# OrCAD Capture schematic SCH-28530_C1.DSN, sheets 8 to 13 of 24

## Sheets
8 08 SYSTEM: size C
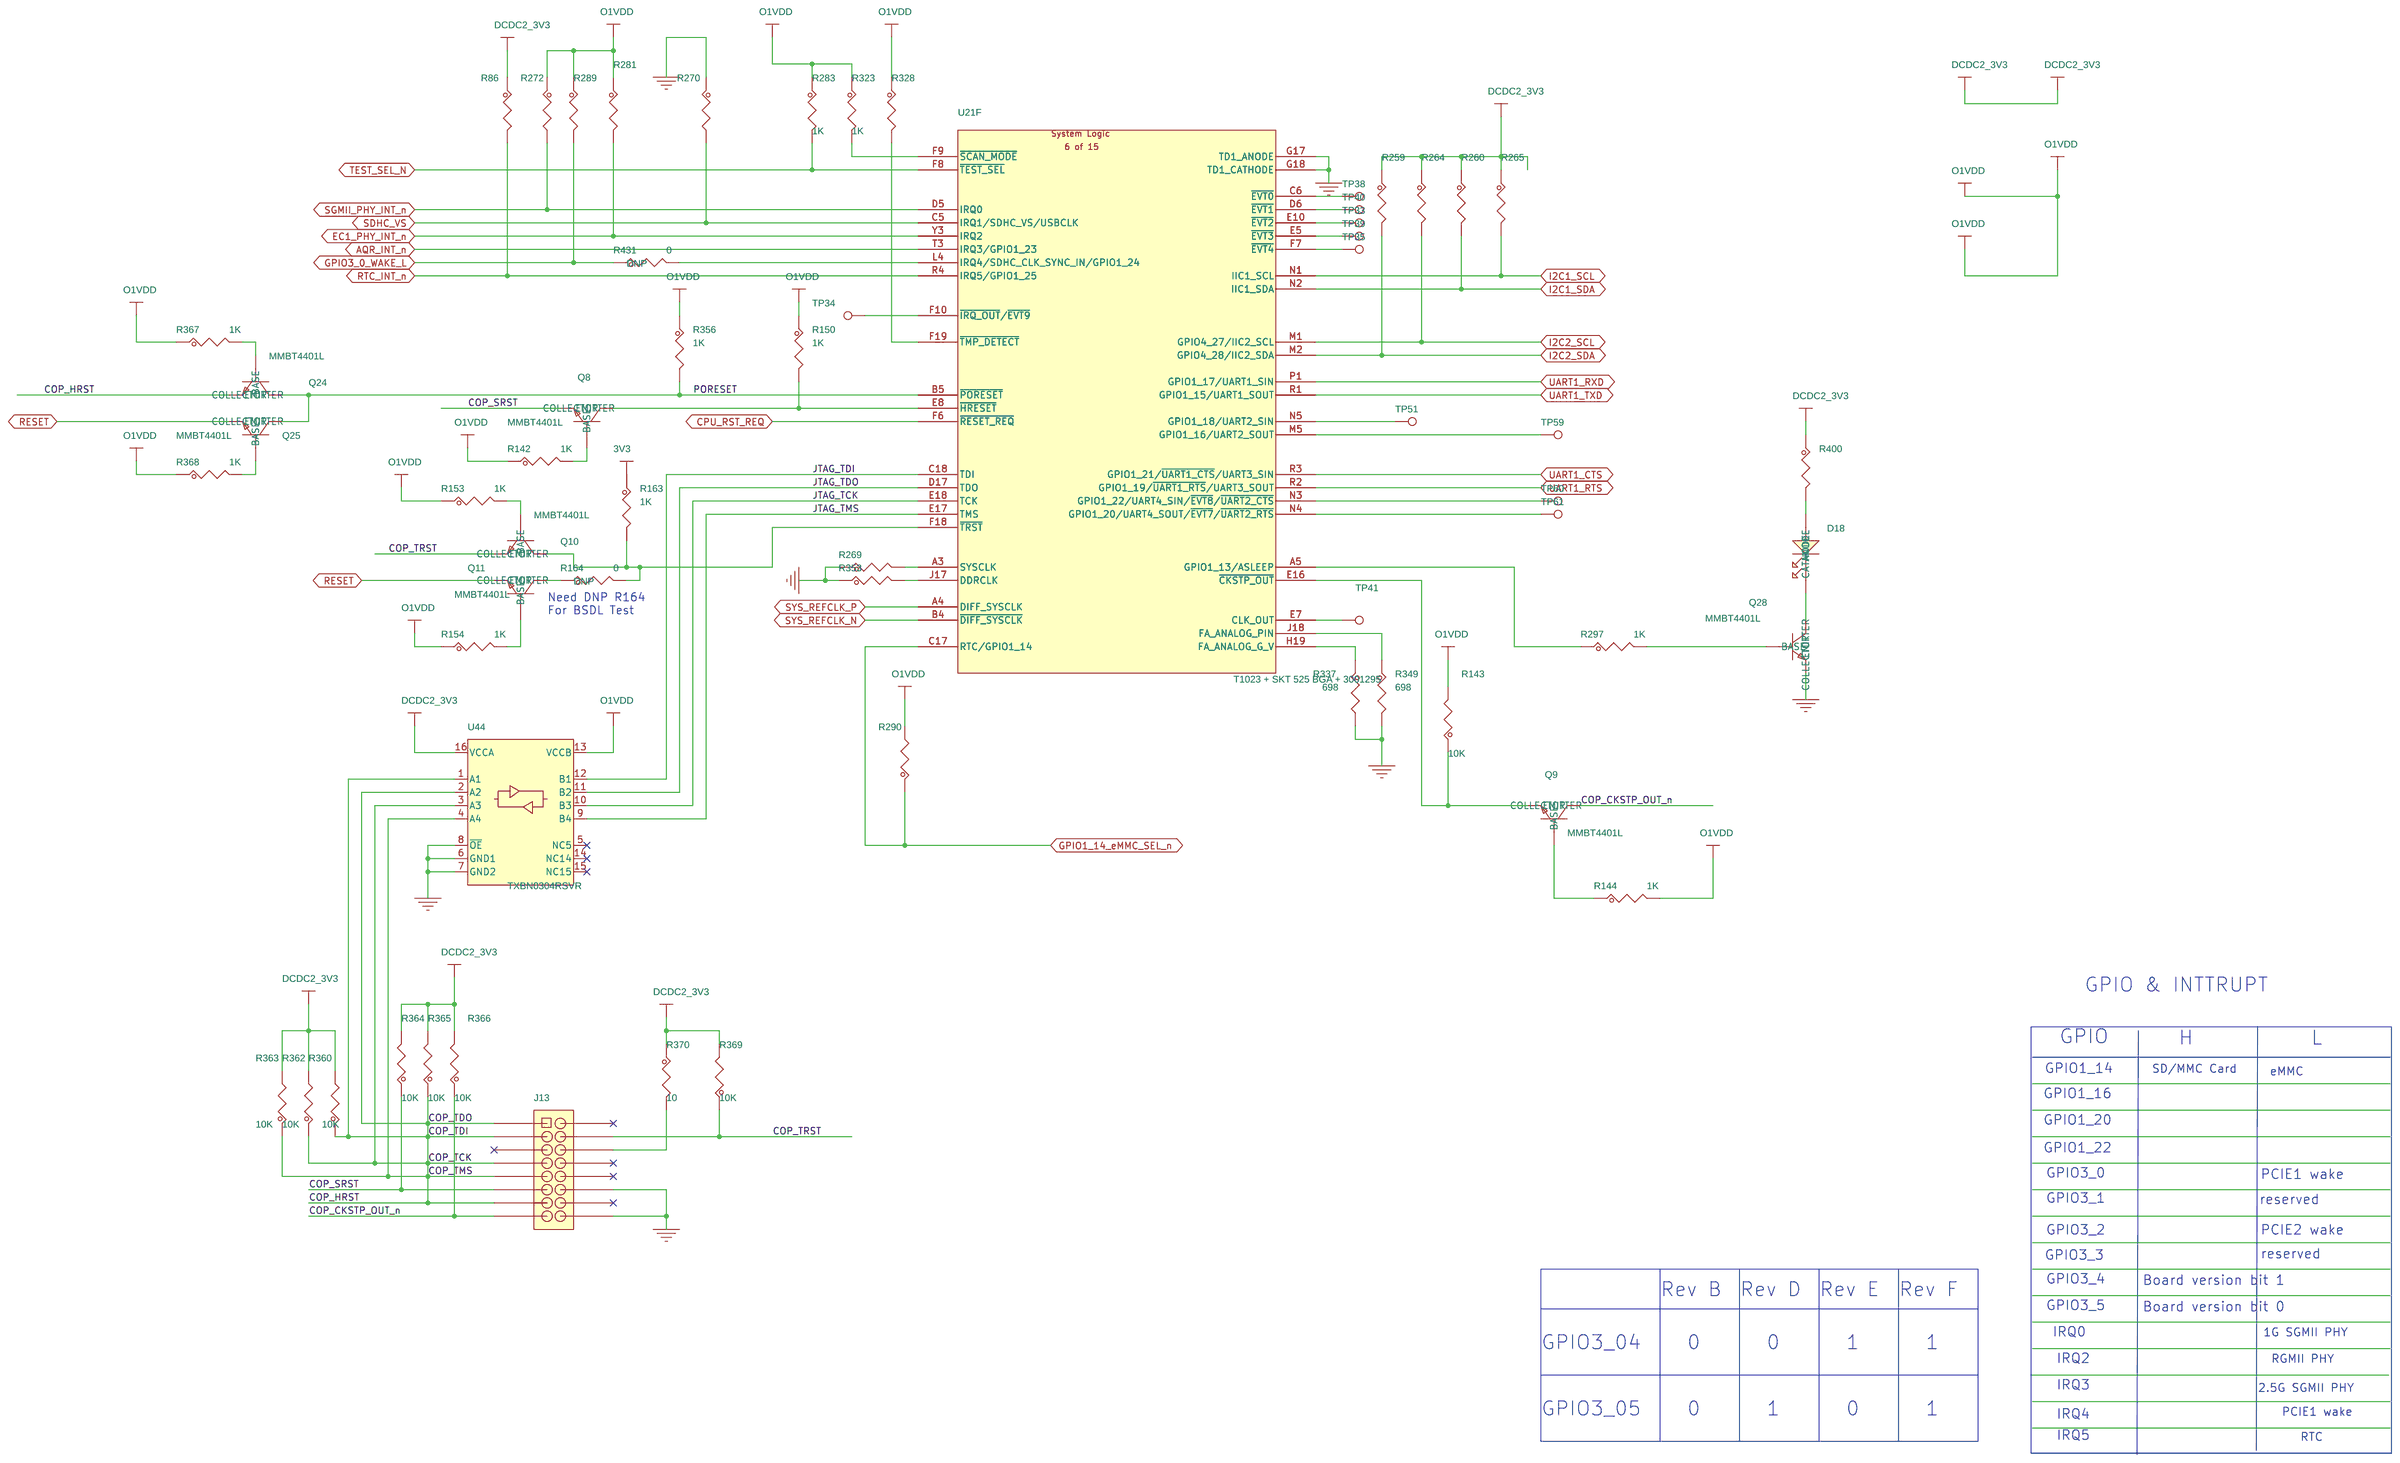
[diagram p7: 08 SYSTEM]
9 09 EC&SerDes: size B
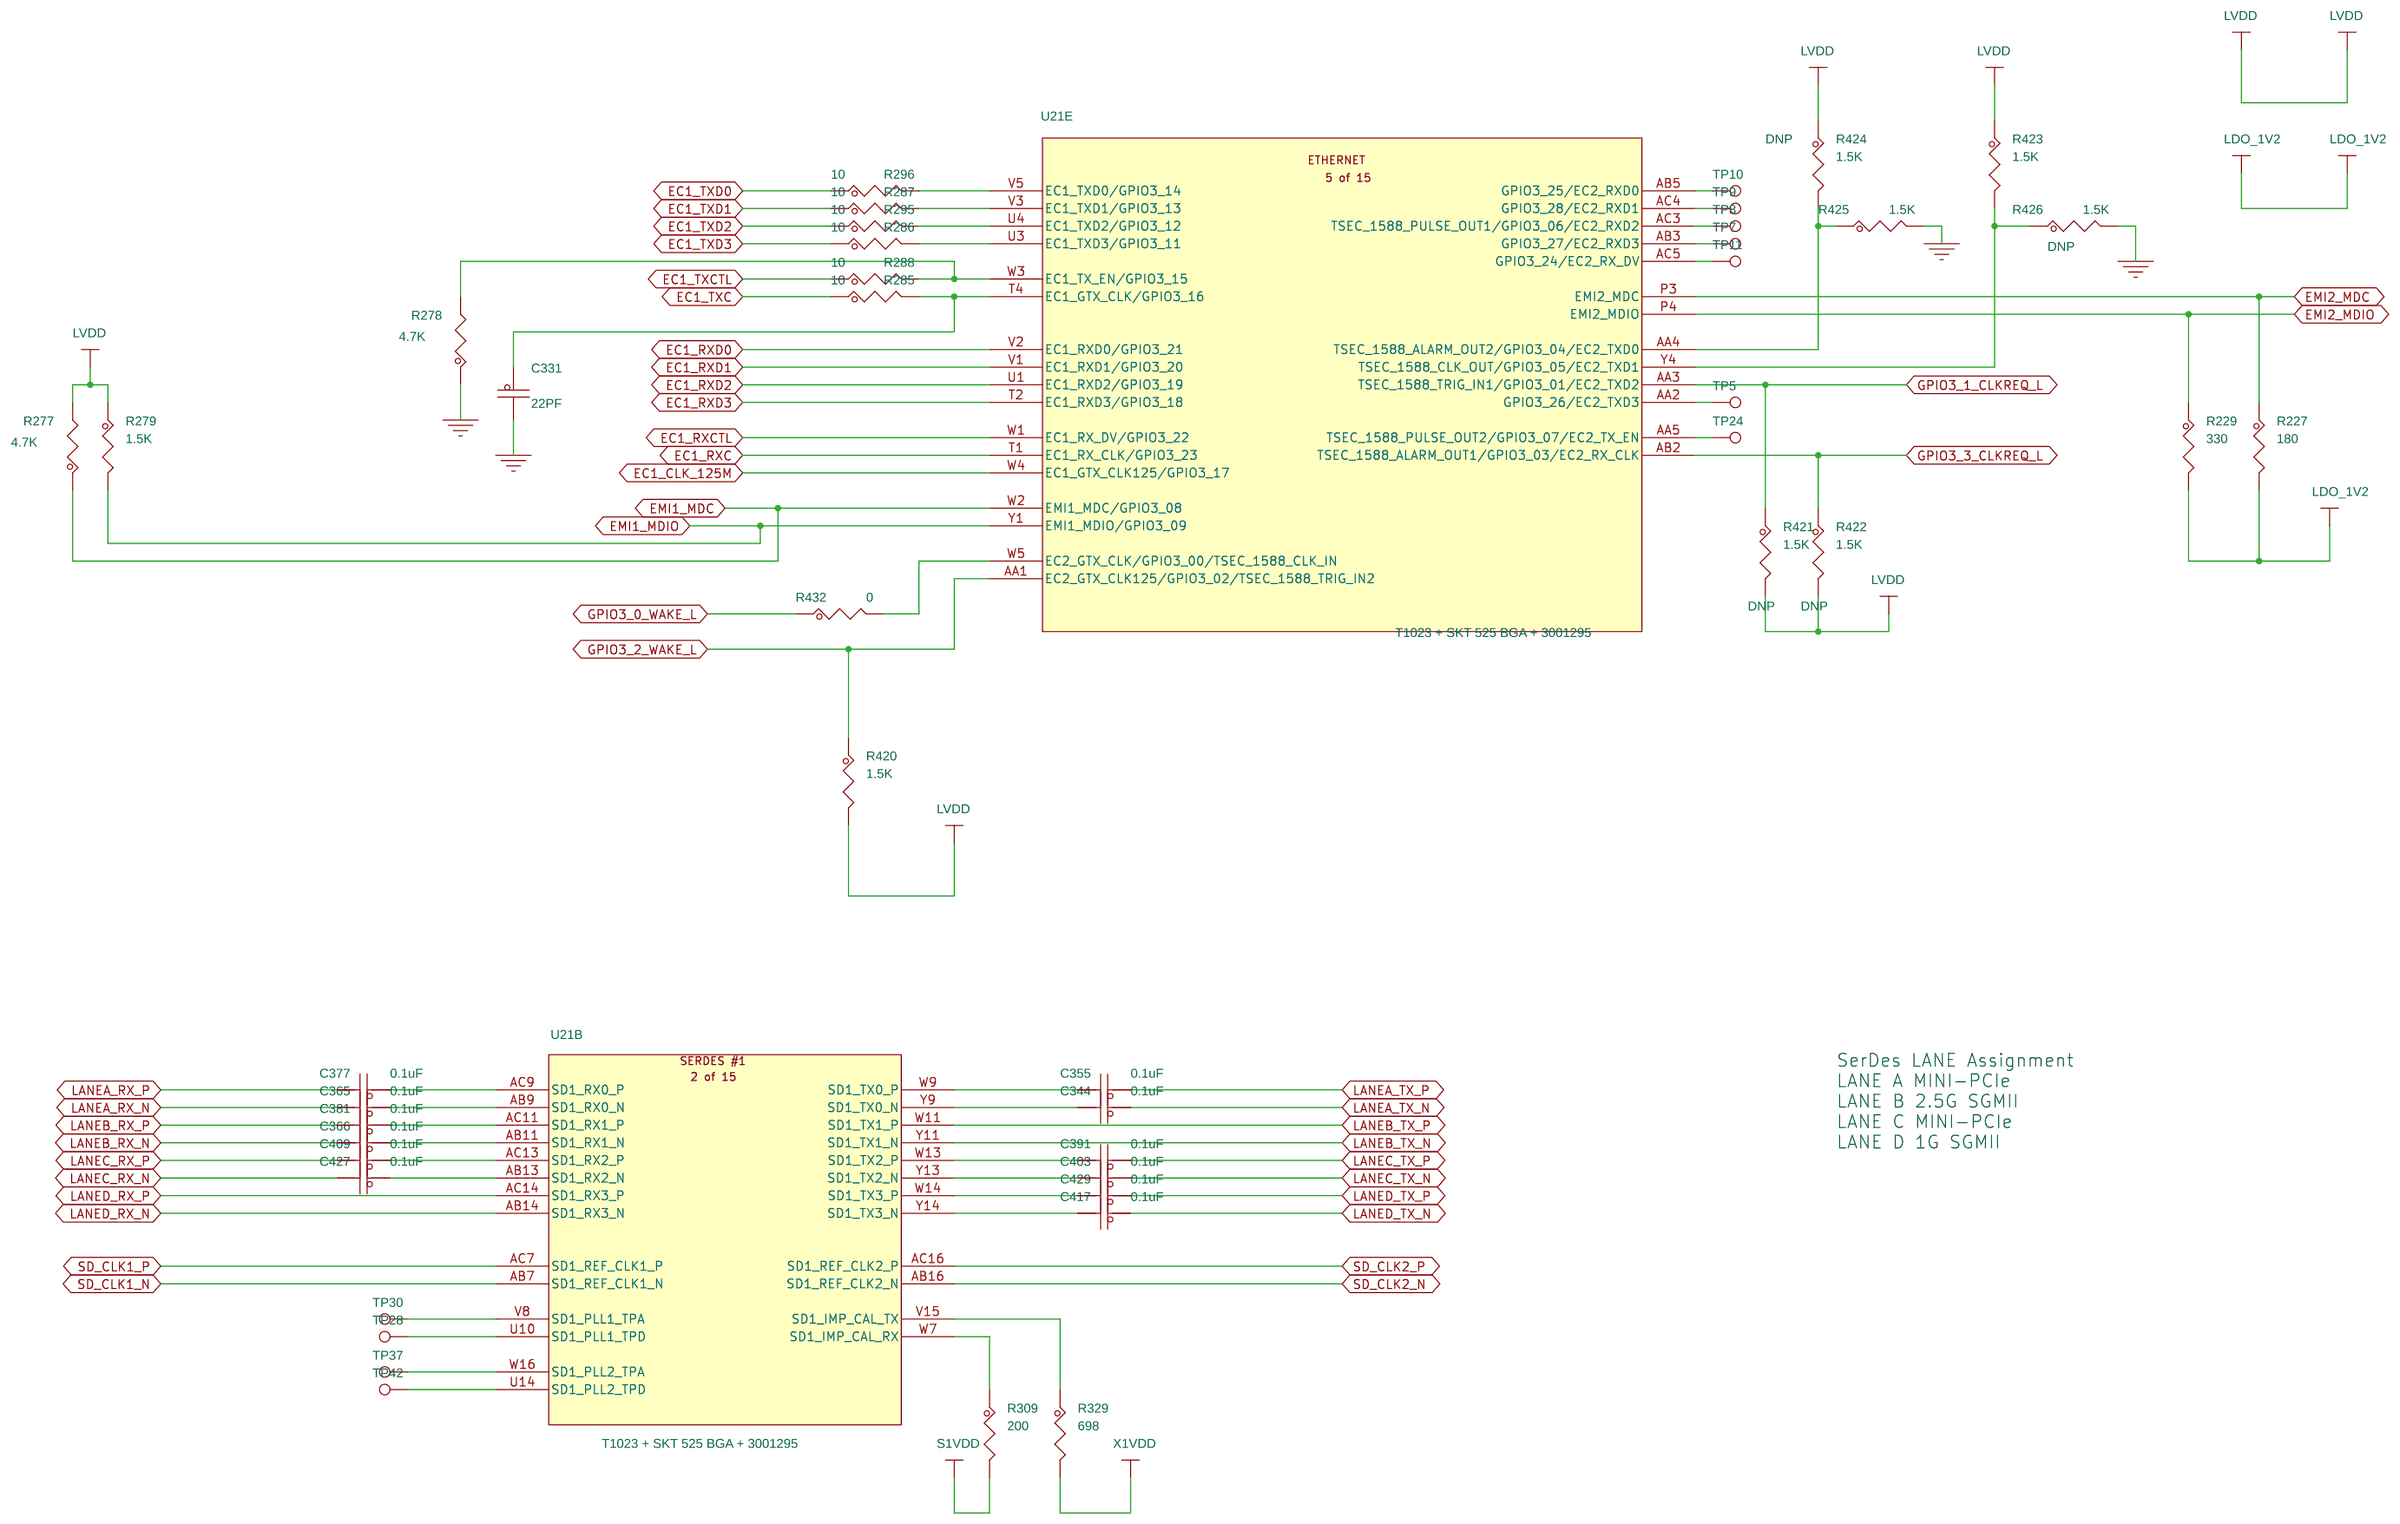
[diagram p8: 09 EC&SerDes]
10 10 USB: size C
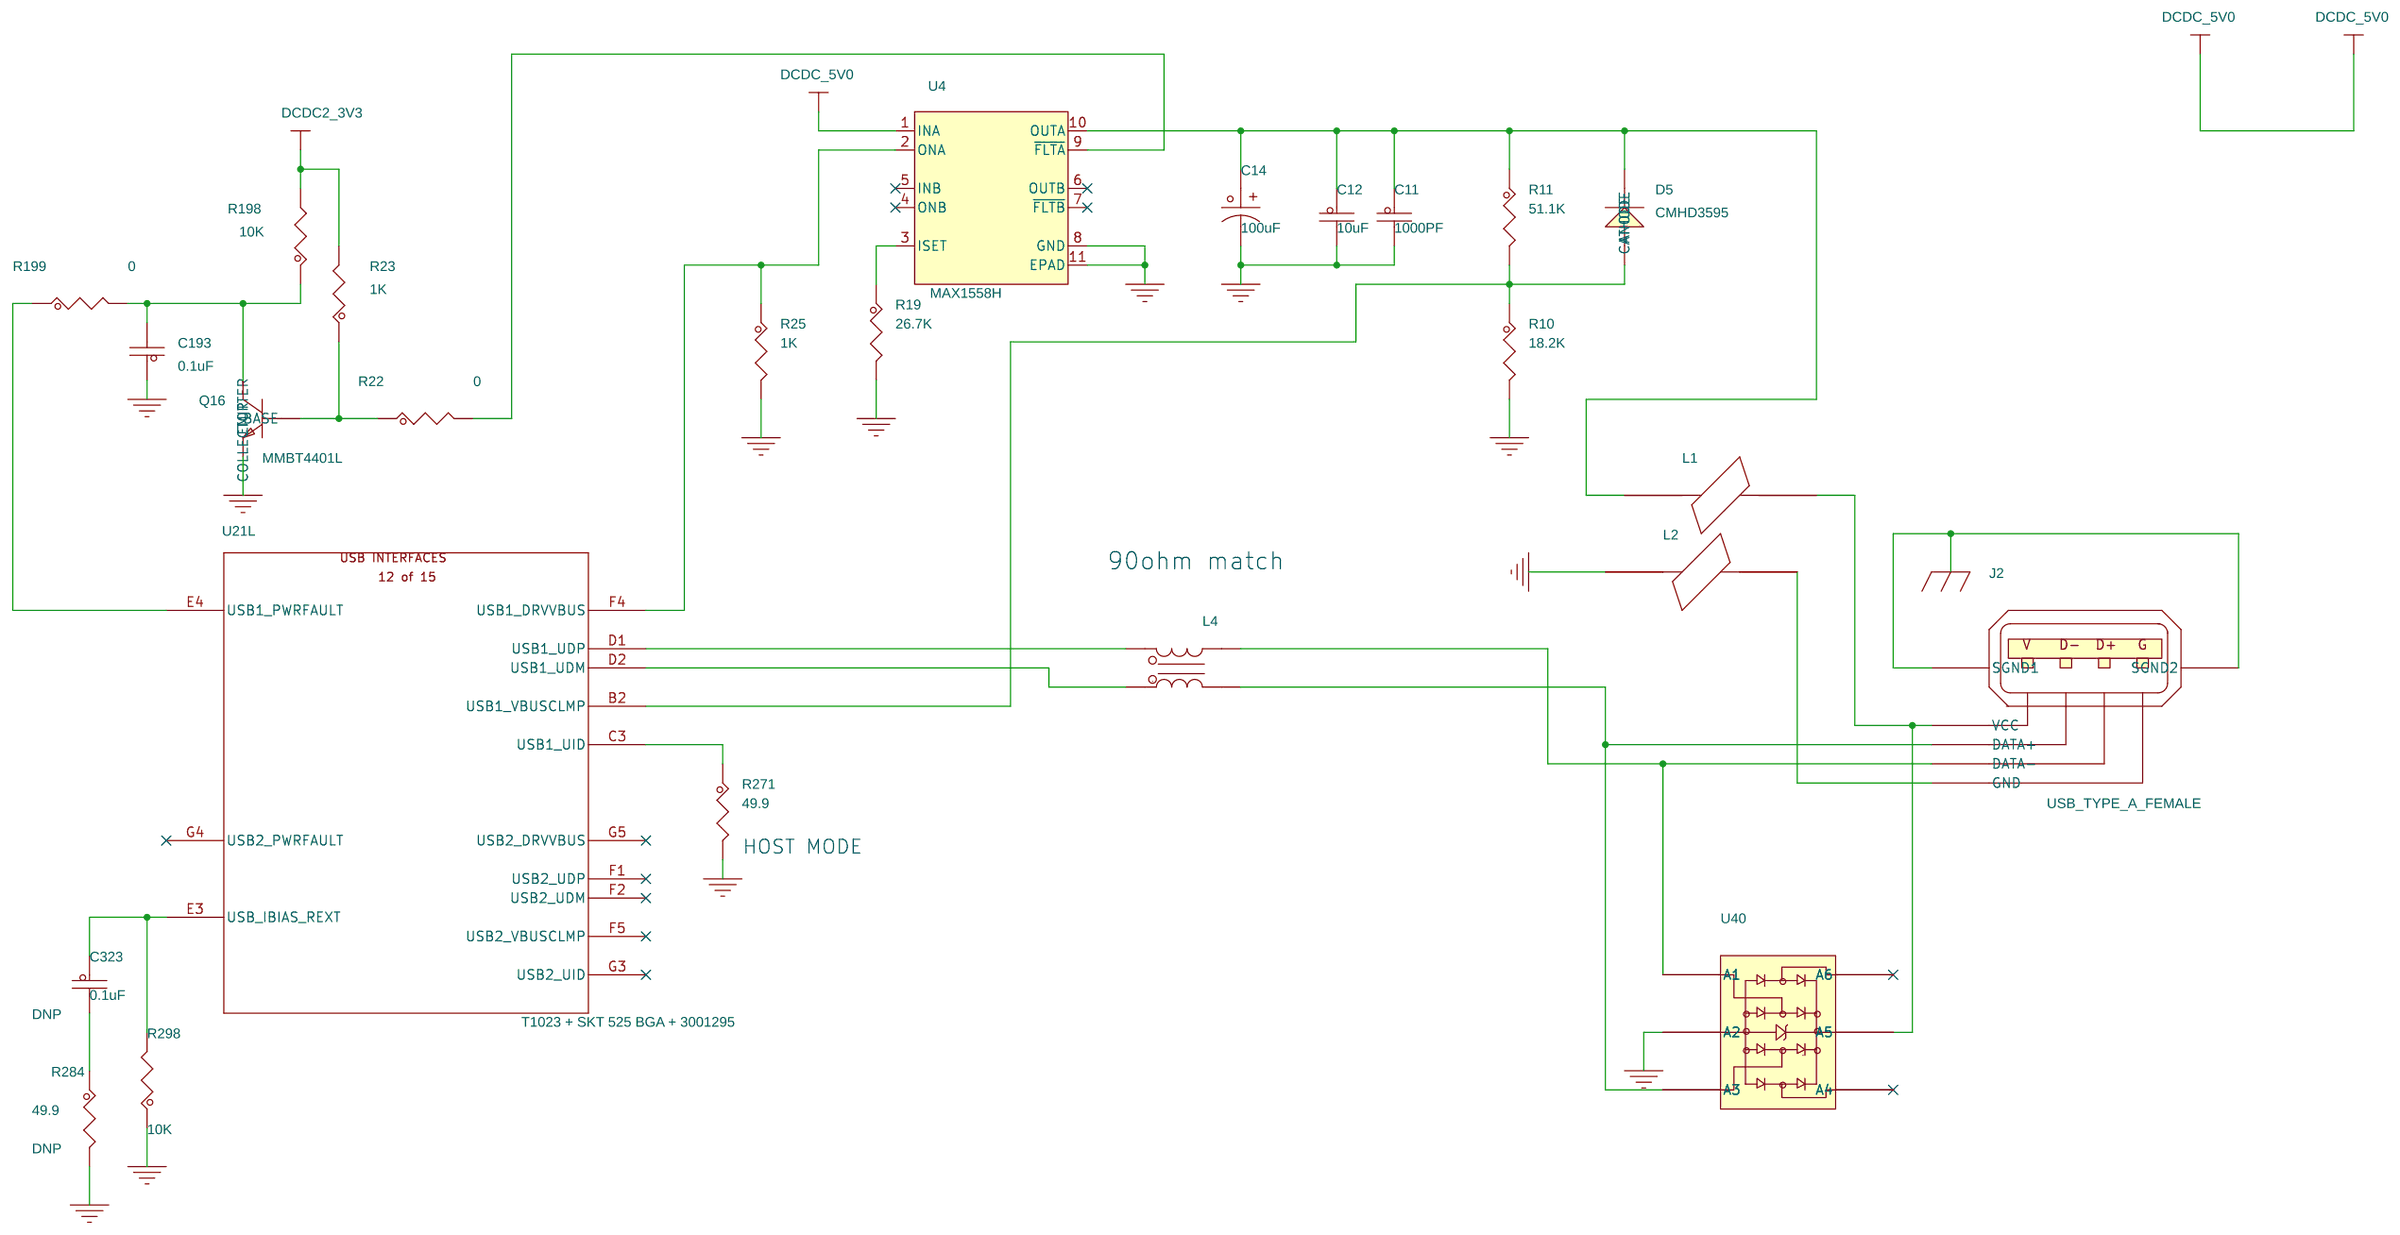
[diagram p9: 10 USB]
11 11 T1023 PWR: size C
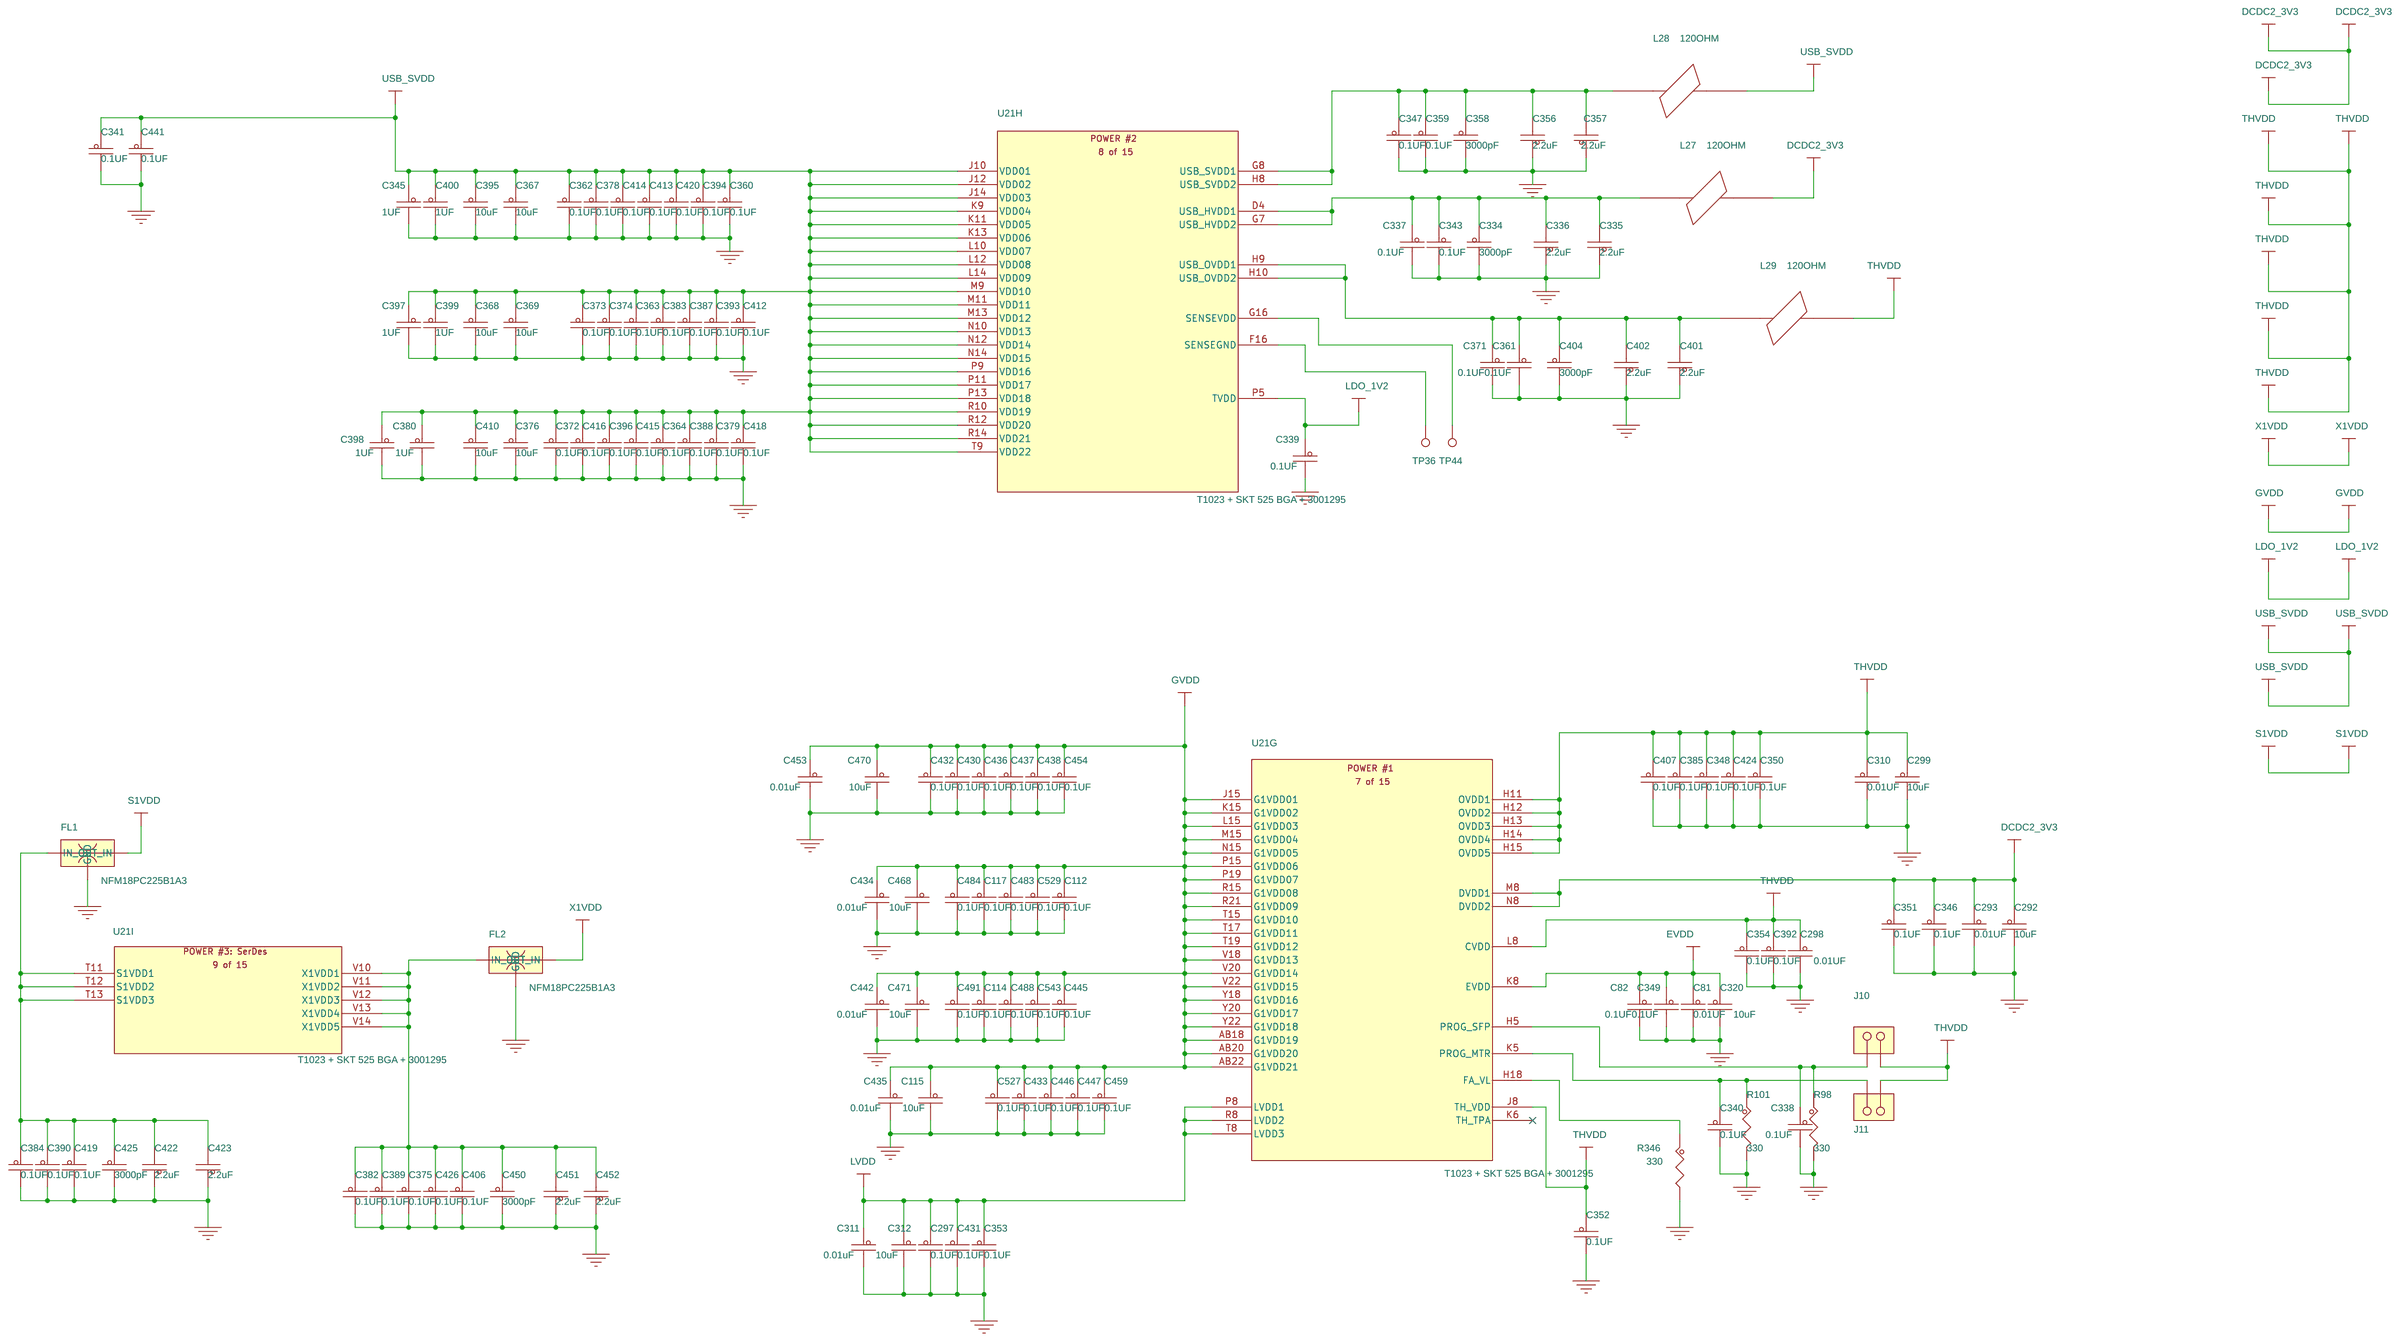
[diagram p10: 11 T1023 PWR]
12 12 T1023 GND: size C
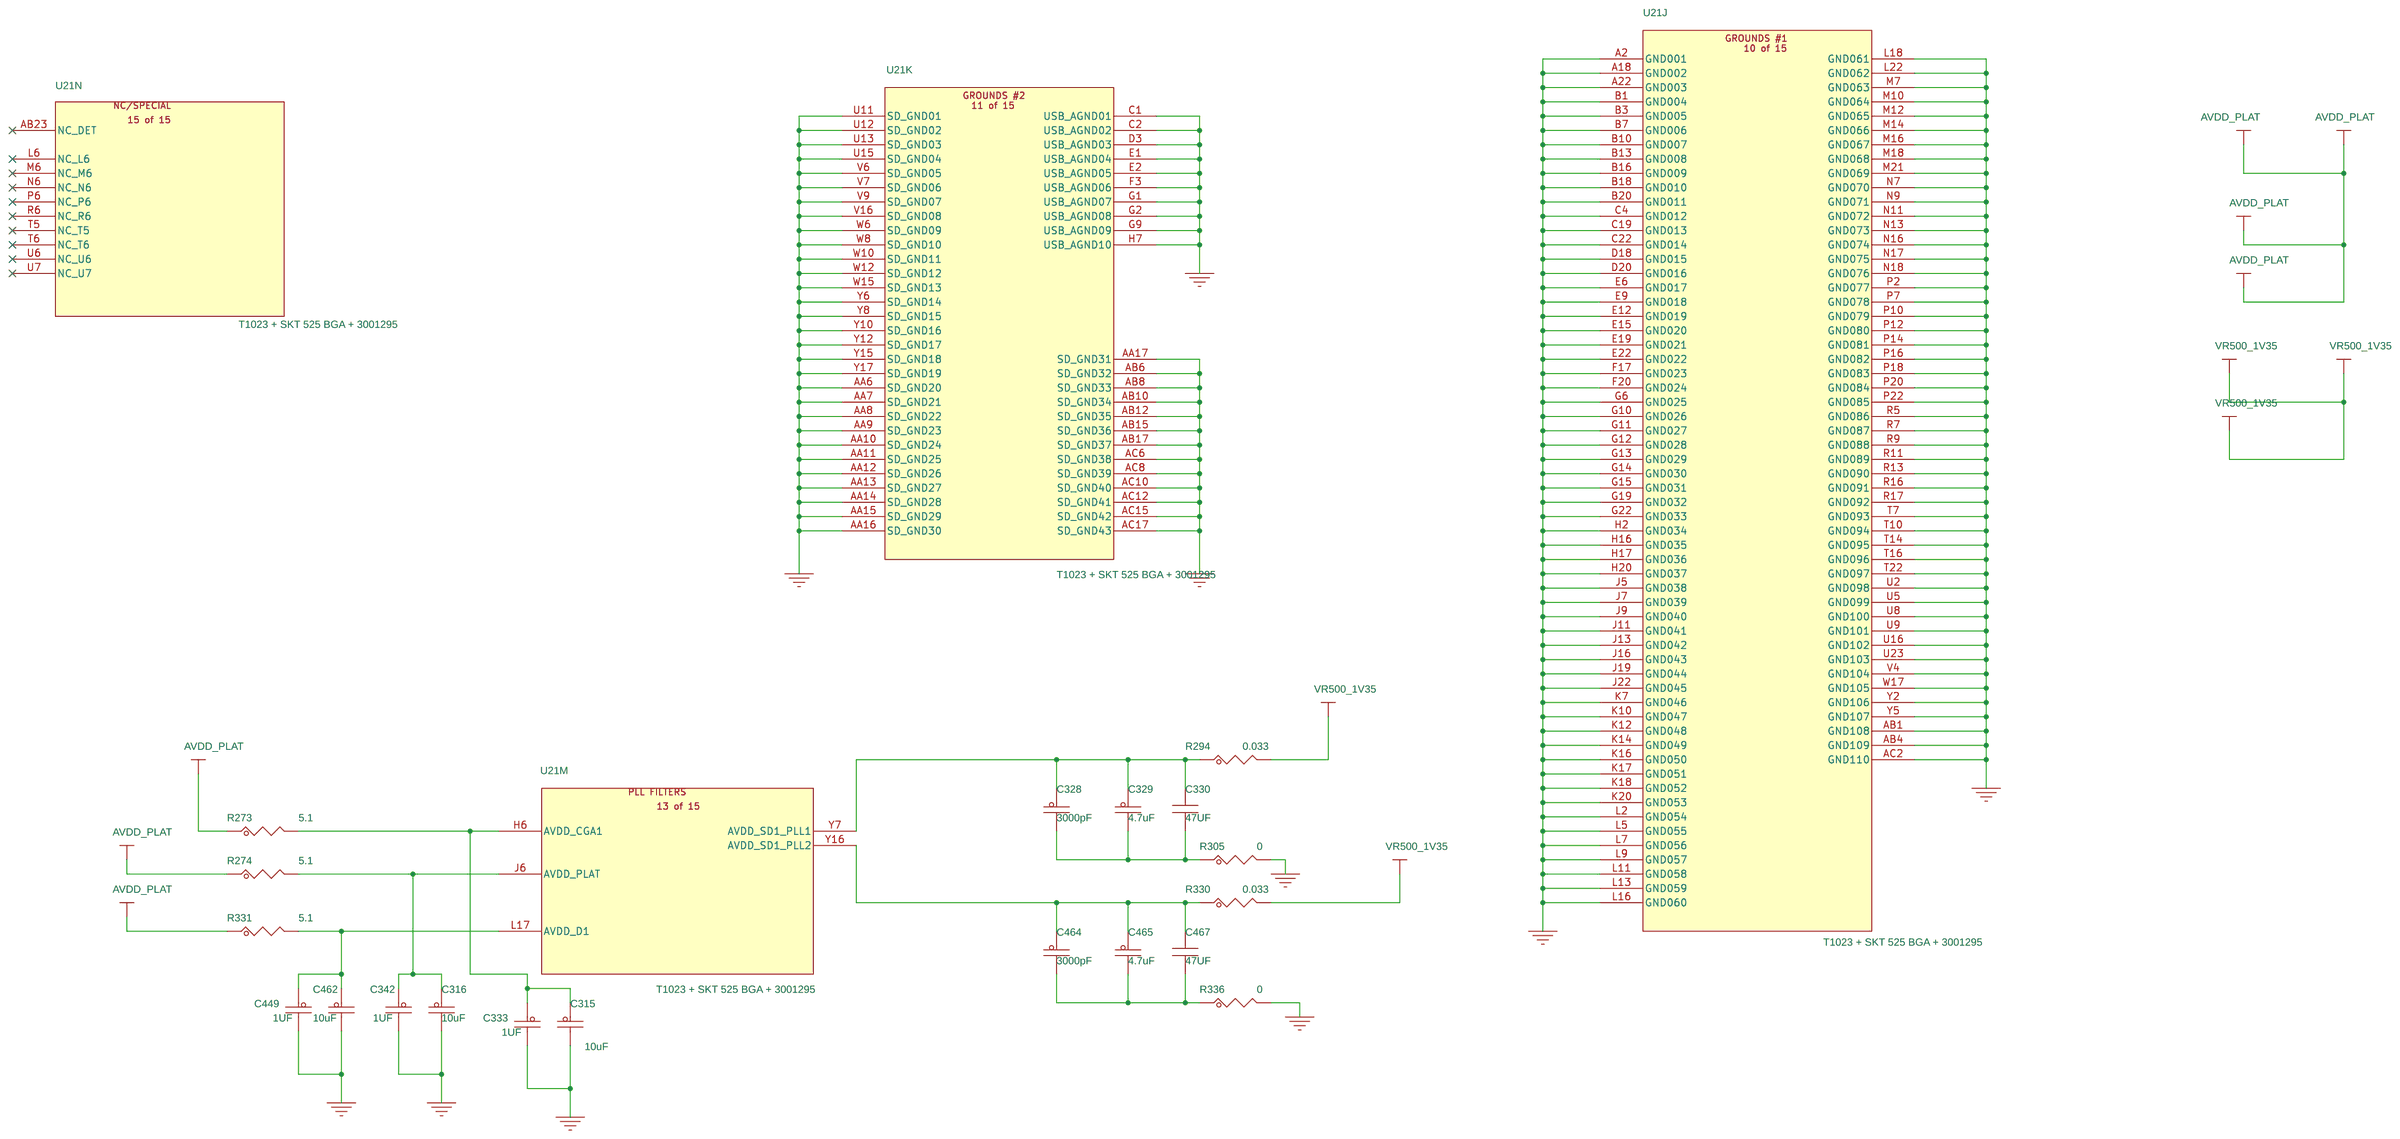
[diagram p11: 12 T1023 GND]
13 13 UART&I2C: size C
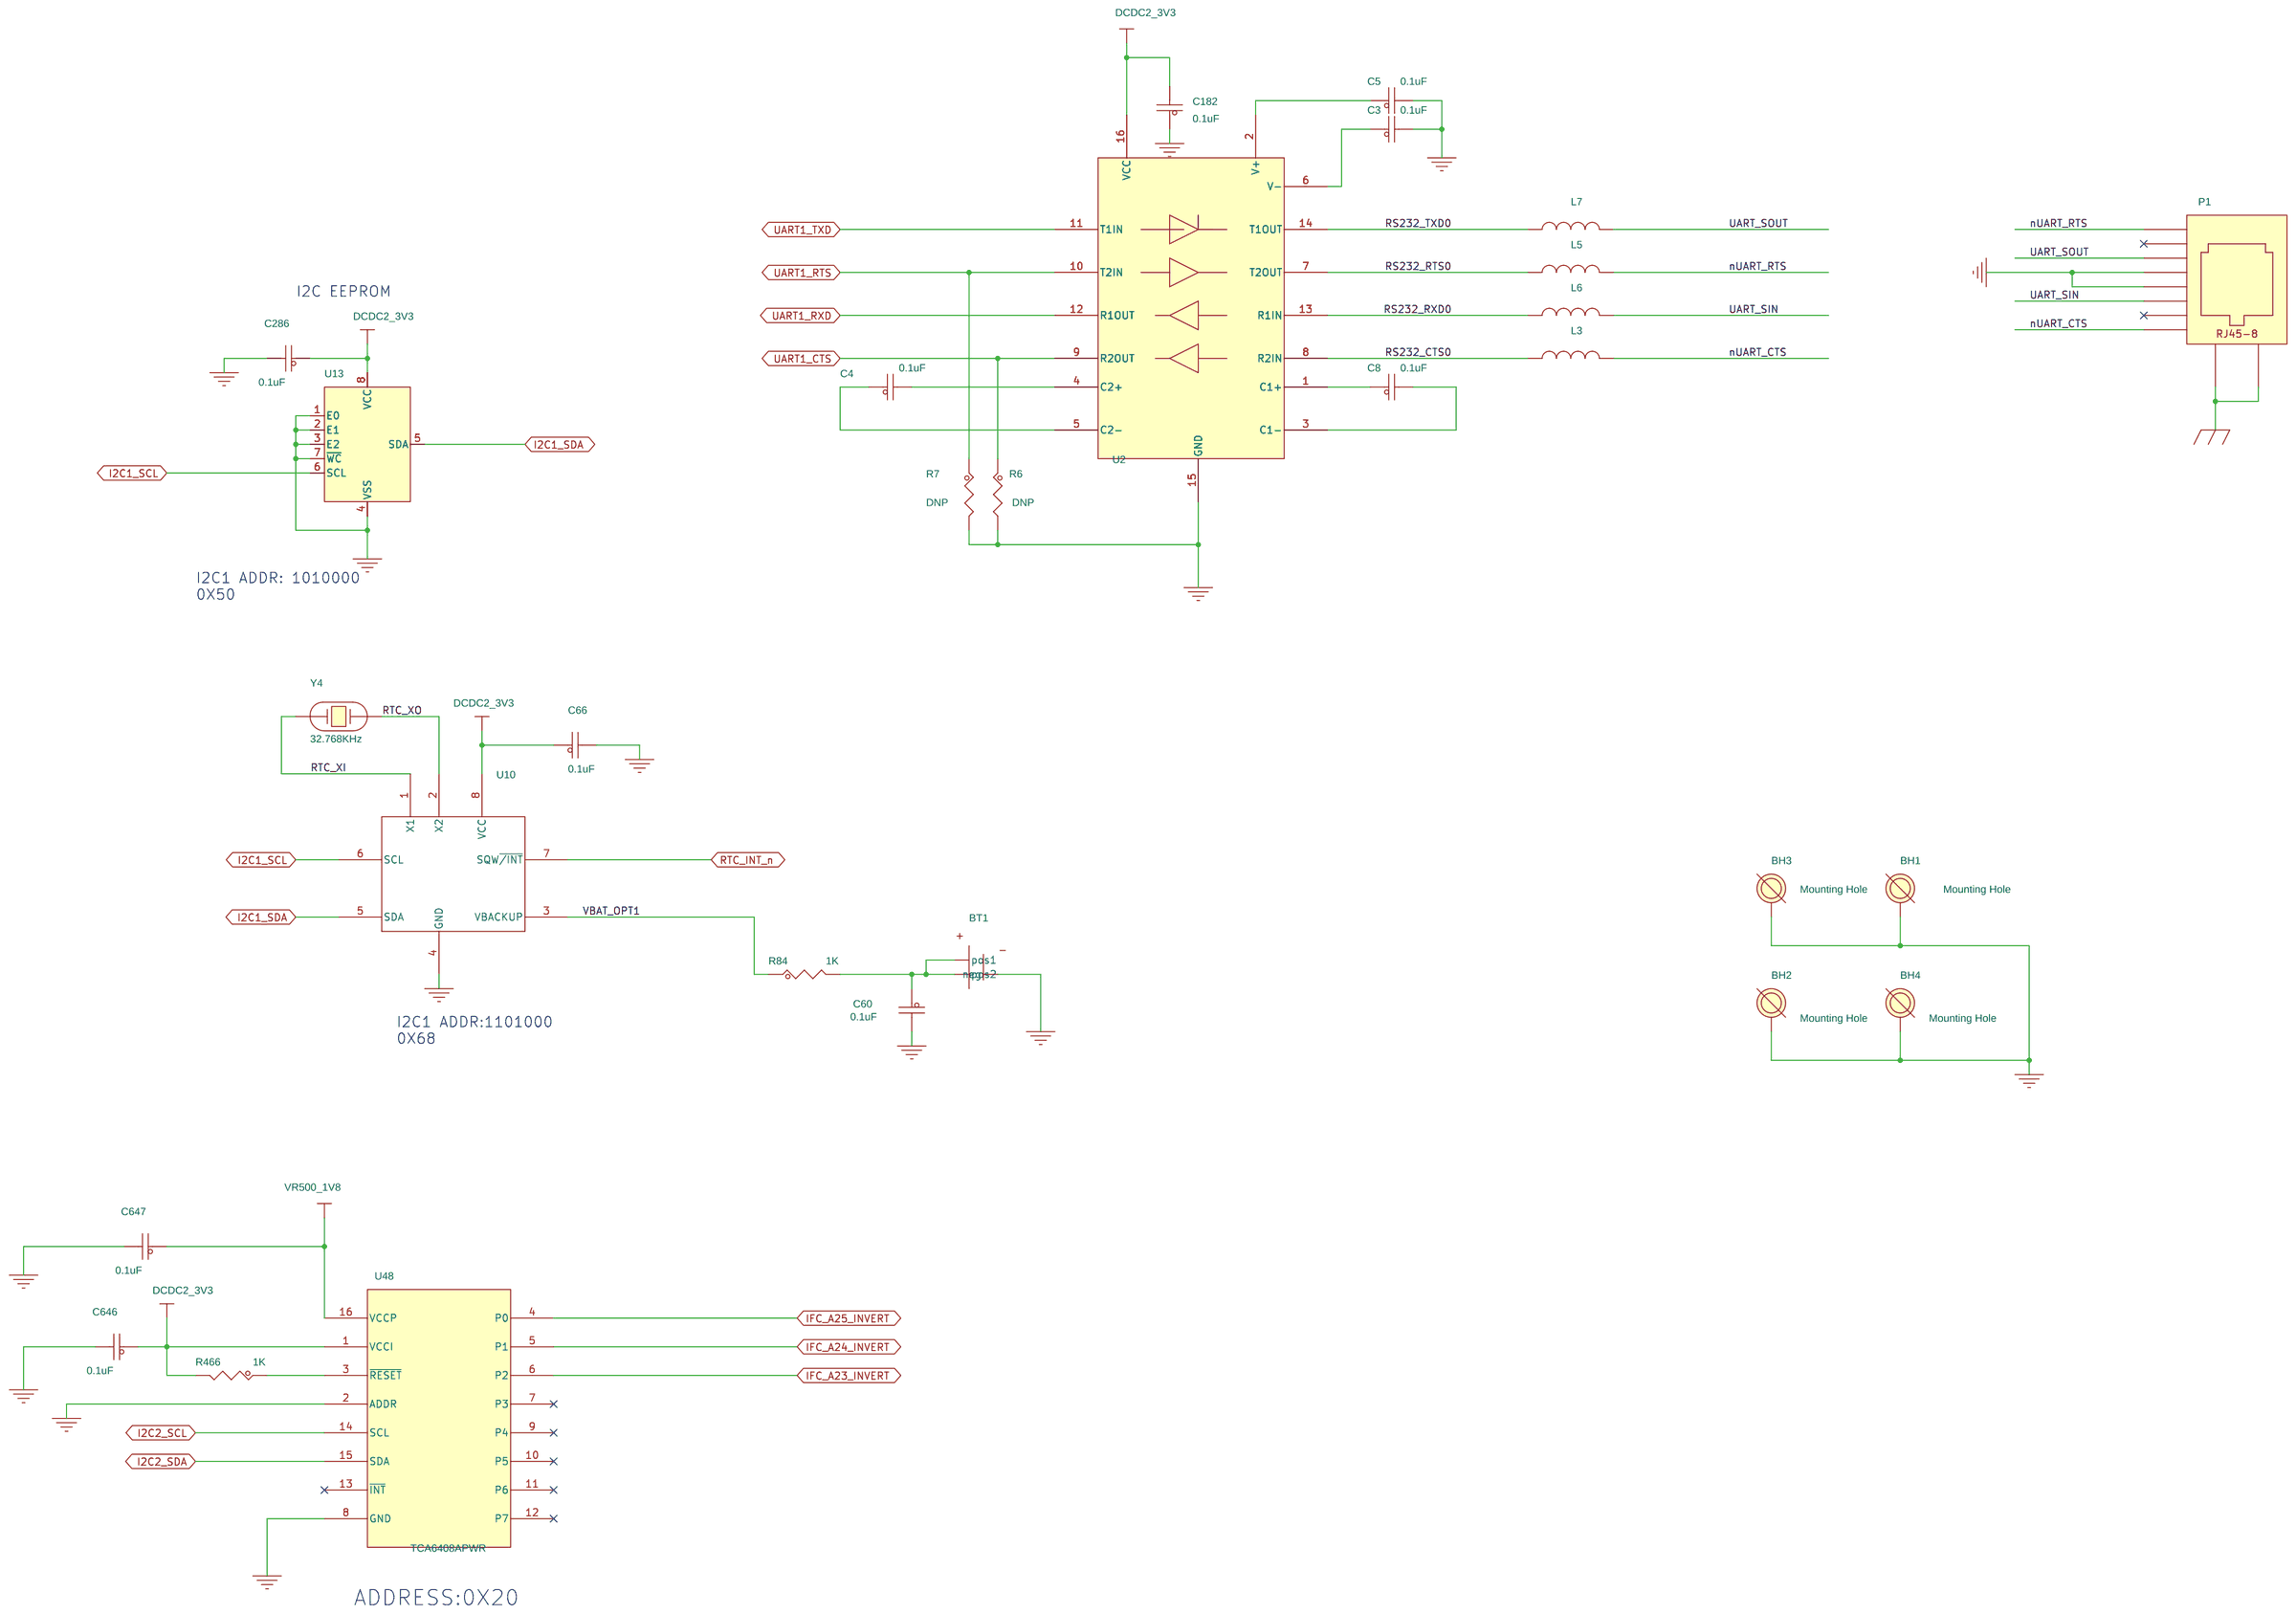
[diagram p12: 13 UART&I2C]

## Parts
sheet 08 SYSTEM
D18  LED_YEL  [led2_2p54_6p6x4p3mm]
J13  HTST-108-01-L-DV  [HDR208_HTST_SM]
Q8  MMBT4401L  [SOT23]
Q9  MMBT4401L  [SOT23]
Q10  MMBT4401L  [SOT23]
Q11  MMBT4401L  [SOT23]
Q24  MMBT4401L  [SOT23]
Q25  MMBT4401L  [SOT23]
Q28  MMBT4401L  [SOT23]
R86  4.7K  [RC0402_25]
R142  1K  [RC0603_OV]
R143  10K  [RC0603_OV]
R144  1K  [RC0603_OV]
R150  1K  [RC0603_OV]
R153  1K  [RC0603_OV]
R154  1K  [RC0603_OV]
R163  1K  [RC0603_OV]
R164  0  [RC0402_25]
R259  4.7K  [RC0402_25]
R260  4.7K  [RC0402_25]
R264  4.7K  [RC0402_25]
R265  4.7K  [RC0402_25]
R269  4.7K  [RC0402_25]
R270  4.7K  [RC0402_25]
R272  4.7K  [RC0402_25]
R281  4.7K  [RC0402_25]
R283  1K  [RC0603_OV]
R289  4.7K  [RC0402_25]
R290  4.7K  [RC0402_25]
R297  1K  [RC0603_OV]
R323  1K  [RC0603_OV]
R328  4.7K  [RC0402_25]
R337  698  [RC0402_25]
R349  698  [RC0402_25]
R353  4.7K  [RC0402_25]
R356  1K  [RC0603_OV]
R360  10K  [RC0603_OV]
R362  10K  [RC0603_OV]
R363  10K  [RC0603_OV]
R364  10K  [RC0603_OV]
R365  10K  [RC0603_OV]
R366  10K  [RC0603_OV]
R367  1K  [RC0603_OV]
R368  1K  [RC0603_OV]
R369  10K  [RC0603_OV]
R370  10  [RC0603_OV]
R400  330  [RC0603_OV]
R431  0  [RC0402_25]
TP33  35 MIL  [TESTPOINT_35MIL]
TP34  35 MIL  [TESTPOINT_35MIL]
TP35  35 MIL  [TESTPOINT_35MIL]
TP38  35 MIL  [TESTPOINT_35MIL]
TP39  35 MIL  [TESTPOINT_35MIL]
TP40  35 MIL  [TESTPOINT_35MIL]
TP41  35 MIL  [TESTPOINT_35MIL]
TP51  35 MIL  [TESTPOINT_35MIL]
TP59  35 MIL  [TESTPOINT_35MIL]
TP60  35 MIL  [TESTPOINT_35MIL]
TP61  35 MIL  [TESTPOINT_35MIL]
U44  TXBN0304RSVR  [pqfn16_0p4_2p65x1p85]
sheet 09 EC&SerDes
C331  22PF  [CC0402_25]
C344  0.1uF  [CC0402_25]
C355  0.1uF  [CC0402_25]
C365  0.1uF  [CC0402_25]
C366  0.1uF  [CC0402_25]
C377  0.1uF  [CC0402_25]
C381  0.1uF  [CC0402_25]
C391  0.1uF  [CC0402_25]
C403  0.1uF  [CC0402_25]
C409  0.1uF  [CC0402_25]
C417  0.1uF  [CC0402_25]
C427  0.1uF  [CC0402_25]
C429  0.1uF  [CC0402_25]
R227  180  [RC0402_25]
R229  330  [RC0402_25]
R277  4.7K  [RC0603_OV]
R278  4.7K  [RC0603_OV]
R279  1.5K  [RC0603_OV]
R285  10  [RC0402_25]
R286  10  [RC0402_25]
R287  10  [RC0402_25]
R288  10  [RC0402_25]
R295  10  [RC0402_25]
R296  10  [RC0402_25]
R309  200  [RC0603_OV]
R329  698  [RC0402_25]
R420  1.5K  [RC0603_OV]
R421  1.5K  [RC0603_OV]
R422  1.5K  [RC0603_OV]
R423  1.5K  [RC0603_OV]
R424  1.5K  [RC0603_OV]
R425  1.5K  [RC0603_OV]
R426  1.5K  [RC0603_OV]
R432  0  [RC0402_25]
TP5  35 MIL  [TESTPOINT_35MIL]
TP7  35 MIL  [TESTPOINT_35MIL]
TP8  35 MIL  [TESTPOINT_35MIL]
TP9  35 MIL  [TESTPOINT_35MIL]
TP10  35 MIL  [TESTPOINT_35MIL]
TP11  35 MIL  [TESTPOINT_35MIL]
TP24  35 MIL  [TESTPOINT_35MIL]
TP28  35 MIL  [TESTPOINT_35MIL]
TP30  35 MIL  [TESTPOINT_35MIL]
TP37  35 MIL  [TESTPOINT_35MIL]
TP42  35 MIL  [TESTPOINT_35MIL]
sheet 10 USB
C11  1000PF  [CC0603_OV]
C12  10uF  [CC0603_OV]
C14  100uF  [cce63x55]
C193  0.1uF  [CC0402_25]
C323  0.1uF  [CC0402_25]
D5  CMHD3595  [sod123_a]
J2  USB_TYPE_A_FEMALE  [USB_A_TH_SAMTEC]
L1  120OHM  [IND_0603]
L2  120OHM  [IND_0603]
L4  90OHM  [ind4_choke_0805]
Q16  MMBT4401L  [SOT23]
R10  18.2K  [RC0603_OV]
R11  51.1K  [RC0603_OV]
R19  26.7K  [RC0603_OV]
R22  0  [RC0603_OV]
R23  1K  [RC0603_OV]
R25  1K  [RC0603_OV]
R198  10K  [RC0603_OV]
R199  0  [RC0603_OV]
R271  49.9  [RC0402_25]
R284  49.9  [RC0402_25]
R298  10K  [RC0603_OV]
U4  MAX1558H  [tdfn10_0p5_3p1x3p1]
U21  T1023 + SKT 525 BGA + 3001295  [SKT_BGA525_0P8_58P6SQ_SM]  (sections A,B,C,D,E,F,G,H,I,J,K,L,M,N)
U40  SRV05-4  [SOT23_S6]
sheet 11 T1023 PWR
C81  0.01UF  [CC0402_25]
C82  0.1UF  [CC0201]
C112  0.1UF  [CC0201]
C114  0.1UF  [CC0201]
C115  10uF  [CC0603_OV]
C117  0.1UF  [CC0201]
C292  10uF  [CC0603_OV]
C293  0.01UF  [CC0402_25]
C297  0.1UF  [CC0201]
C298  0.01UF  [CC0402_25]
C299  10uF  [CC0603_OV]
C310  0.01UF  [CC0402_25]
C311  0.01uF  [CC0201]
C312  10uF  [CC0603_OV]
C320  10uF  [CC0603_OV]
C334  3000pF  [CC0603_OV]
C335  2.2uF  [CC0402_25]
C336  2.2uF  [CC0402_25]
C337  0.1UF  [CC0201]
C338  0.1UF  [CC0201]
C339  0.1UF  [CC0201]
C340  0.1UF  [CC0201]
C341  0.1UF  [CC0201]
C343  0.1UF  [CC0201]
C345  1UF  [CC0402_25]
C346  0.1UF  [CC0201]
C347  0.1UF  [CC0201]
C348  0.1UF  [CC0201]
C349  0.1UF  [CC0201]
C350  0.1UF  [CC0201]
C351  0.1UF  [CC0201]
C352  0.1UF  [CC0201]
C353  0.1UF  [CC0201]
C354  0.1UF  [CC0201]
C356  2.2uF  [CC0402_25]
C357  2.2uF  [CC0402_25]
C358  3000pF  [CC0603_OV]
C359  0.1UF  [CC0201]
C360  0.1UF  [CC0201]
C361  0.1UF  [CC0201]
C362  0.1UF  [CC0201]
C363  0.1UF  [CC0201]
C364  0.1UF  [CC0201]
C367  10uF  [CC0603_OV]
C368  10uF  [CC0603_OV]
C369  10uF  [CC0603_OV]
C371  0.1UF  [CC0201]
C372  0.1UF  [CC0201]
C373  0.1UF  [CC0201]
C374  0.1UF  [CC0201]
C375  0.1UF  [CC0201]
C376  10uF  [CC0603_OV]
C378  0.1UF  [CC0201]
C379  0.1UF  [CC0201]
C380  1UF  [CC0402_25]
C382  0.1UF  [CC0201]
C383  0.1UF  [CC0201]
C384  0.1UF  [CC0201]
C385  0.1UF  [CC0201]
C387  0.1UF  [CC0201]
C388  0.1UF  [CC0201]
C389  0.1UF  [CC0201]
C390  0.1UF  [CC0201]
C392  0.1UF  [CC0201]
C393  0.1UF  [CC0201]
C394  0.1UF  [CC0201]
C395  10uF  [CC0603_OV]
C396  0.1UF  [CC0201]
C397  1UF  [CC0402_25]
C398  1UF  [CC0402_25]
C399  1UF  [CC0402_25]
C400  1UF  [CC0402_25]
C401  2.2uF  [CC0402_25]
C402  2.2uF  [CC0402_25]
C404  3000pF  [CC0603_OV]
C406  0.1UF  [CC0201]
C407  0.1UF  [CC0201]
C410  10uF  [CC0603_OV]
C412  0.1UF  [CC0201]
C413  0.1UF  [CC0201]
C414  0.1UF  [CC0201]
C415  0.1UF  [CC0201]
C416  0.1UF  [CC0201]
C418  0.1UF  [CC0201]
C419  0.1UF  [CC0201]
C420  0.1UF  [CC0201]
C422  2.2uF  [CC0402_25]
C423  2.2uF  [CC0402_25]
C424  0.1UF  [CC0201]
C425  3000pF  [CC0603_OV]
C426  0.1UF  [CC0201]
C430  0.1UF  [CC0201]
C431  0.1UF  [CC0201]
C432  0.1UF  [CC0201]
C433  0.1UF  [CC0201]
C434  0.01uF  [CC0201]
C435  0.01uF  [CC0201]
C436  0.1UF  [CC0201]
C437  0.1UF  [CC0201]
C438  0.1UF  [CC0201]
C441  0.1UF  [CC0201]
C442  0.01uF  [CC0201]
C445  0.1UF  [CC0201]
C446  0.1UF  [CC0201]
C447  0.1UF  [CC0201]
C450  3000pF  [CC0603_OV]
C451  2.2uF  [CC0402_25]
C452  2.2uF  [CC0402_25]
C453  0.01uF  [CC0201]
C454  0.1UF  [CC0201]
C459  0.1UF  [CC0201]
C468  10uF  [CC0603_OV]
C470  10uF  [CC0603_OV]
C471  10uF  [CC0603_OV]
C483  0.1UF  [CC0201]
C484  0.1UF  [CC0201]
C488  0.1UF  [CC0201]
C491  0.1UF  [CC0201]
C527  0.1UF  [CC0201]
C529  0.1UF  [CC0201]
C543  0.1UF  [CC0201]
FL1  NFM18PC225B1A3  [cc0603_nfm18pc]
FL2  NFM18PC225B1A3  [cc0603_nfm18pc]
J10  HDR 1X2  [HDR102]
J11  HDR 1X2  [HDR102]
L27  120OHM  [IND_0603]
L28  120OHM  [IND_0603]
L29  120OHM  [IND_0603]
R98  330  [RC0402_25]
R101  330  [RC0402_25]
R346  330  [RC0402_25]
TP36  35 MIL  [TESTPOINT_35MIL]
TP44  35 MIL  [TESTPOINT_35MIL]
sheet 12 T1023 GND
C315  10uF  [CC0603_OV]
C316  10uF  [CC0603_OV]
C328  3000pF  [CC0603_OV]
C329  4.7uF  [CC0603_OV]
C330  47UF  [CC1210]
C333  1UF  [CC0402_25]
C342  1UF  [CC0402_25]
C449  1UF  [CC0402_25]
C462  10uF  [CC0603_OV]
C464  3000pF  [CC0603_OV]
C465  4.7uF  [CC0603_OV]
C467  47UF  [CC1210]
R273  5.1  [RC0402_25]
R274  5.1  [RC0402_25]
R294  0.033  [RC0603_OV]
R305  0  [RC0402_25]
R330  0.033  [RC0603_OV]
R331  5.1  [RC0402_25]
R336  0  [RC0402_25]
sheet 13 UART&I2C
BH1  Mounting Hole  [mh175-125p]
BH2  Mounting Hole  [mh175-125p]
BH3  Mounting Hole  [mh175-125p]
BH4  Mounting Hole  [mh175-125p]
BT1  WBA-3B2 U  [skt_bat_225x886_3V]
C3  0.1uF  [CC0402_25]
C4  0.1uF  [CC0402_25]
C5  0.1uF  [CC0402_25]
C8  0.1uF  [CC0402_25]
C60  0.1uF  [CC0402_25]
C66  0.1uF  [CC0402_25]
C182  0.1uF  [CC0402_25]
C286  0.1uF  [CC0402_25]
C646  0.1uF  [CC0402_25]
C647  0.1uF  [CC0402_25]
L3  1000OHM  [IND_0402]
L5  1000OHM  [IND_0402]
L6  1000OHM  [IND_0402]
L7  1000OHM  [IND_0402]
P1  RJ45  [con8_rj45_1p02_16x17]
R6  4.7K  [RC0402_25]
R7  4.7K  [RC0402_25]
R84  1K  [RC0603_OV]
R466  1K  [RC0603_OV]
U2  SP3232  [SSOP16]
U10  DS1339U-33+  [usop-8]
U13  M24256-BWDW6TP  [TSSOP8]
U48  TCA6408APWR  [tssop16]
Y4  32.768KHz  [xtl2_tf_sm]

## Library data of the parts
D18 = LED: LED YEL SGL RA 30MA TH; AGILE_PN: 370-76481; CAD_APPROVED: Yes; HEIGHT: 7.55MM; MFG_NAME01: KINGBRIGHT; MFG_PN01: L-7104EW/1YD-SH; ROHS: Yes
J13 = HTST-108-01-L-DV: HDR 2X8 SMT 25MIL PIN 0.1IN CTR  AU; AGILE_PN: 211-75198; CAD_APPROVED: Yes; HEIGHT: 10.65mm; MFG_NAME01: SAMTEC; ROHS: Yes
Q8-Q11 Q16 Q24 Q25 Q28 = NPN: TRAN NPN SW 600MA 40V AEC-Q101 SOT23; AGILE_PN: 480-75087; CAD_APPROVED: Yes; HEIGHT: 1.11MM; MFG_NAME01: ON SEMICONDUCTOR; MFG_PN01: MMBT4401LT1G; ROHS: Yes
R86 R259 R260 R264 R265 R269 R270 R272 R281 R289 R328 R353 = RES: RES MF 4.7K 1/16W 5% 0402; AGILE_PN: 470-75626; CAD_APPROVED: Yes; FPLIST: RC0402_25,RC0402_HD,0402_CC; Function: UART; HEIGHT: 0.41mm; MFG_NAME01: KOA SPEER; MFG_PN01: RK73B1ETTP472J; ROHS: Yes; SIGNAL_MODEL: DEFAULT_RESISTOR_4700OHM_2_1; TOL: 5%; Tolerance: 5%
R23 R25 R84 R142 R144 R150 R153 R154 R163 R283 R297 R323 R356 R367 R368 R466 = RES: RES MF 1K 1/10W 1% 0603; AGILE_PN: 470-80784; CAD_APPROVED: Yes; FPLIST: RC0603_OV,RC0603,0603_CC; HEIGHT: 0.55MM; MFG_NAME01: VIKING TECH CORPORATION; MFG_PN01: AR03FTNX1001; ROHS: Yes; Tolerance: 1%
R143 R198 R298 R360 R362-R366 R369 = RES: RES MF 10K 1/10W 5% 0603; AGILE_PN: 470-75410; CAD_APPROVED: Yes; FPLIST: RC0603_OV,RC0603,0603_CC; HEIGHT: 0.55MM; MFG_NAME01: KOA SPEER; MFG_PN01: RK73B1JTTD103J; ROHS: Yes; Tolerance: 5%
R164 R431 = RES: RES MF ZERO OHM 1/10W -- 0402; AGILE_PN: 470-79965; ASSY_OPT: DNP; CAD_APPROVED: Yes; FPLIST: RC0402_25,RC0402_HD,RC0402_X2,0402_CC; HEIGHT: 0.4MM; MFG_NAME01: Panasonic; MFG_PN01: ERJ-2GE0R00X; ROHS: Yes
R290 = RES: RES MF 4.7K 1/16W 5% 0402; AGILE_PN: 470-75626; CAD_APPROVED: Yes; FPLIST: RC0402_25,RC0402_HD,0402_CC; HEIGHT: 0.41mm; ICA_MFR_NAME: <ICA_MFR_NAME>; MFG_NAME01: KOA SPEER; MFG_PN01: RK73B1ETTP472J; ROHS: Yes; SIGNAL_MODEL: DEFAULT_RESISTOR_33OHM_2_1; Tolerance: 5%
R329 R337 R349 = RES: RES MF 698 OHM 1/16W 1% ACE-Q200 0402; AGILE_PN: 470-78342; CAD_APPROVED: Yes; FPLIST: RC0402_25,RC0402_HD,0402_CC; HEIGHT: 0.4MM; MFG_NAME01: KOA SPEER; MFG_PN01: RK73H1ETTP6980F; ROHS: Yes; Tolerance: 1%
R370 = RES: RES MF 10.0 OHM 1/10W 1% 0603; AGILE_PN: 470-75423; CAD_APPROVED: Yes; FPLIST: RC0603_OV,RC0603,0603_CC; HEIGHT: 0.55MM; MFG_NAME01: KOA SPEER; MFG_PN01: RK73H1JTTD10R0F; ROHS: Yes; Tolerance: 1%
R400 = RES: RES MF 330 OHM 1/10W 1% 0603; AGILE_PN: 470-75512; CAD_APPROVED: Yes; FPLIST: RC0603_OV,RC0603,0603_CC; HEIGHT: 0.55 MM; MFG_NAME01: KOA SPEER; MFG_PN01: RK73H1JTTD3300F; ROHS: Yes; SIGNAL_MODEL: DEFAULT_RESISTOR_330OHM_2_1; TOL: 1%; Tolerance: 1%
TP5 TP7-TP11 TP24 TP28 TP30 TP33-TP42 TP44 TP51 TP59-TP61 = Test_pad: TEST PAD 35 MIL ROUND SMT; NO PART TO ORDER; AGILE_PN: 510-75219; CAD_APPROVED: Yes; HEIGHT: 0.1 MM; ROHS: Yes
U44 = TXBN0304_QFN16: IC VXLTR 4-BIT BIDIR 0.9-3.6V PQFN16; AGILE_PN: 312-80668; CAD_APPROVED: Yes; HEIGHT: 0.55 MM; MFG_NAME01: TEXAS INSTRUMENTS; ROHS: Yes
C331 = CAP_NP: CAP CER 22PF 50V 5% C0G 0402; AGILE_PN: 150-75266; CAD_APPROVED: Yes; FPLIST: CC0402_25,CC0402_HD,0402_CC; HEIGHT: 0.635MM; MFG_NAME01: AVX; MFG_PN01: 04025A220JAT2A; ROHS: Yes; Tolerance: 5%; VOLTAGE: 50V
C344 C355 C365 C366 C377 C381 C391 C403 C409 C417 C427 C429 = CAP_NP: CAP CER 0.1UF 25V 10% X5R 0402; AGILE_PN: 150-78633; CAD_APPROVED: Yes; FPLIST: CC0402_25,CC0402_HD,0402_CC; HEIGHT: 0.55MM; MFG_NAME01: YAGEO AMERICA; MFG_PN01: CC0402KRX5R8BB104; ROHS: Yes; SIGNAL_MODEL: DEFAULT_CAPACITOR_1e+07pF_2_1; Tolerance: 10%; VOLTAGE: 25V
R227 = RES: RES MF 180 OHM 1/16W 1% 0402; AGILE_PN: 470-30765; CAD_APPROVED: Yes; FPLIST: RC0402_25,RC0402_HD,0402_CC; HEIGHT: 0.40 MM; MFG_NAME01: KOA SPEER; MFG_PN01: RK73H1ETTP1800F; ROHS: Yes; Tolerance: 1%
R98 R101 R229 R346 = RES: RES MF 330 OHM 1/16W 5% 0402; AGILE_PN: 470-75613; CAD_APPROVED: Yes; FPLIST: RC0402_25,RC0402_HD,0402_CC; HEIGHT: 0.41mm; MFG_NAME01: VISHAY INTERTECHNOLOGY; MFG_PN01: CRCW0402330RJNED; ROHS: Yes; Tolerance: 5%
R277 R278 = RES: RES MF 4.7K 1/10W 5% 0603; AGILE_PN: 470-75414; CAD_APPROVED: Yes; FPLIST: RC0603_OV,RC0603,0603_CC; HEIGHT: 0.55 MM; MFG_NAME01: VISHAY INTERTECHNOLOGY; MFG_PN01: CRCW06034K70JNEA; ROHS: Yes; Tolerance: 5%
R279 R420 R423 R425 = RES: RES MF 1.5K 1/10W 5% 0603; AGILE_PN: 470-75995; CAD_APPROVED: YES; FPLIST: RC0603_OV,RC0603,0603_CC; HEIGHT: 0.55 MM; MFG_NAME01: BOURNS; MFG_PN01: CR0603-JW-152ELF; ROHS: Yes; Tolerance: 5%
R285-R288 R295 R296 = RES: RES MF 10 OHM 1/16W 5% 0402; AGILE_PN: 470-75589; CAD_APPROVED: Yes; FPLIST: RC0402_25,RC0402_HD,0402_CC; HEIGHT: 0.4MM; MFG_NAME01: VENKEL COMPANY; MFG_PN01: CR0402-16W-100JT; ROHS: Yes; Tolerance: 5%
R309 = RES: RES MF 200 OHM 1/10W 1% 0603; AGILE_PN: 470-30029; CAD_APPROVED: Yes; FPLIST: RC0603_OV,RC0603,0603_CC; HEIGHT: 0.6 MM; MFG_NAME01: KOA SPEER; MFG_PN01: RK73H1JTTD2000F; ROHS: Yes; Tolerance: 1%
R421 R422 R424 R426 = RES: RES MF 1.5K 1/10W 5% 0603; AGILE_PN: 470-75995; ASSY_OPT: DNP; CAD_APPROVED: YES; FPLIST: RC0603_OV,RC0603,0603_CC; HEIGHT: 0.55 MM; MFG_NAME01: BOURNS; MFG_PN01: CR0603-JW-152ELF; ROHS: Yes; Tolerance: 5%
R305 R336 R432 = RES: RES MF ZERO OHM 1/10W -- 0402; AGILE_PN: 470-79965; CAD_APPROVED: Yes; FPLIST: RC0402_25,RC0402_HD,RC0402_X2,0402_CC; HEIGHT: 0.4MM; MFG_NAME01: Panasonic; MFG_PN01: ERJ-2GE0R00X; ROHS: Yes
C11 = CAP_NP: CAP CER 1000PF 50V 5% C0G 0603; AGILE_PN: 150-78519; CAD_APPROVED: Yes; FPLIST: CC0603_OV,CC0603,0603_CC; HEIGHT: 0.9MM; MFG_NAME01: MURATA; MFG_PN01: GRM1885C1H102JA01D; ROHS: Yes; Tolerance: 5%; VOLTAGE: 50V
C12 C115 C292 C299 C312 C315 C316 C320 C367-C369 C376 C395 C410 C462 C468 C470 C471 = CAP_NP: CAP CER 10uF 25V 20% X5R 0603; AGILE_PN: 150-79272; CAD_APPROVED: Yes; FPLIST: CC0603_OV,CC0603,0603_CC; HEIGHT: 1MM; MFG_NAME01: Murata; MFG_PN01: GRM188R61E106MA73D; ROHS: Yes; Tolerance: 20%; VOLTAGE: 25V
C14 = CAP_POL: CAP ALEL 100uF 16V 20% -- SMD; AGILE_PN: 150-78723; CAD_APPROVED: Yes; HEIGHT: 5.5MM; MFG_NAME01: LELON ELECTRONICS CORP; MFG_PN01: VE-101M1CTR-0605; ROHS: Yes; Tolerance: 20%; VOLTAGE: 16V
C3-C5 C8 C182 C193 = CAP_NP: CAP CER 0.1UF 25V 10% X5R 0402; AGILE_PN: 150-78633; CAD_APPROVED: Yes; FPLIST: CC0402_25,CC0402_HD,0402_CC; HEIGHT: 0.55MM; MFG_NAME01: YAGEO AMERICA; MFG_PN01: CC0402KRX5R8BB104; ROHS: Yes; Tolerance: 10%; VOLTAGE: 25V
C323 = CAP_NP: CAP CER 0.1uF 6.3V 10% X5R 0402; AGILE_PN: 150-79388; ASSY_OPT: DNP; CAD_APPROVED: Yes; FPLIST: CC0402_25,CC0402_HD,0402_CC; HEIGHT: 0.55MM; MFG_NAME01: TDK; MFG_PN01: C1005X5R0J104K050BA; ROHS: Yes; Tolerance: 10%; VOLTAGE: 6.3V
D5 = DIODE: DIODE SW 150MA 150V SOD123; AGILE_PN: 480-78080; CAD_APPROVED: Yes; HEIGHT: 1.35MM; MFG_NAME01: CENTRAL SEMICONDUCTOR; MFG_PN01: CMHD3595 BK LEAD FREE; ROHS: Yes
J2 = USB_A: CON 4 SKT RA TH USB A FEMALE; AGILE_PN: 210-75879; CAD_APPROVED: YES; FPLIST: USB_A_TH_SAMTEC,USB_A_TH_SAMTEC_A; HEIGHT: 6.95 MM; MFG_NAME01: SAMTEC; MFG_PN01: USB-A-S-S-B-TH; ROHS: Yes
L1 L2 = BEAD_FERRITE: IND FER BEAD 120OHM@100MHZ 2A 25% 0603; AGILE_PN: 180-30008; CAD_APPROVED: Yes; FPLIST: IND_0603,0603_CC; HEIGHT: 0.95MM; MFG_NAME01: MURATA; MFG_PN01: BLM18PG121SH1; PART_TYPE: FERRITE; ROHS: Yes; SIGNAL_MODEL: DEFAULT_RESISTOR_120OHM_2_1; Tolerance: 25%
L4 = DLW43: IND CHK 90 OHM@100MHZ 330MA 25% 0805; AGILE_PN: 180-76336; CAD_APPROVED: Yes; HEIGHT: 1MM; MFG_NAME01: MURATA; MFG_PN01: DLW21HN900SQ2L; PART_TYPE: CHOKE; ROHS: Yes; Tolerance: 25%
R10 = RES: RES MF 18.2K 1/10W 1% 0603; AGILE_PN: 470-75798; CAD_APPROVED: Yes; FPLIST: RC0603_OV,RC0603,0603_CC; HEIGHT: 0.55 MM; MFG_NAME01: KOA SPEER; MFG_PN01: RK73H1JTTD1822F; ROHS: Yes; Tolerance: 1%
R11 = RES: RES MF 51.1K 1/10W 1% 0603; AGILE_PN: 470-75433; CAD_APPROVED: Yes; FPLIST: RC0603_OV,RC0603,0603_CC; HEIGHT: 0.55 MM; MFG_NAME01: KOA SPEER; MFG_PN01: RK73H1JTTD5112F; ROHS: Yes; Tolerance: 1%
R19 = RES: RES MF 26.7K 1/10W 1% 0603; AGILE_PN: 470-76049; CAD_APPROVED: Yes; FPLIST: RC0603_OV,RC0603,0603_CC; HEIGHT: 0.55 MM; MFG_NAME01: KOA SPEER; MFG_PN01: RK73H1JTTD2672F; ROHS: Yes; Tolerance: 1%
R22 R199 = RES: RES MF ZERO OHM 1/10W -- 0603; AGILE_PN: 470-80866; FPLIST: RC0603_OV,RC0603,R603-X2,0603_CC; HEIGHT: 0.6MM; MFG_NAME01: BOURNS; MFG_PN01: CR0603J/000ELF; ROHS: Yes
R271 = RES: RES MF 49.9 OHM 1/16W 1% 0402; AGILE_PN: 470-75360; CAD_APPROVED: Yes; FPLIST: RC0402_25,RC0402_HD,0402_CC; HEIGHT: 0.4MM; MFG_NAME01: BOURNS; MFG_PN01: CR0402-FX-49R9GLF; ROHS: Yes; Tolerance: 1%
R284 = RES: RES MF 49.9 OHM 1/16W 1% 0402; AGILE_PN: 470-75360; ASSY_OPT: DNP; CAD_APPROVED: Yes; FPLIST: RC0402_25,RC0402_HD,0402_CC; HEIGHT: 0.4MM; MFG_NAME01: BOURNS; MFG_PN01: CR0402-FX-49R9GLF; ROHS: Yes; Tolerance: 1%
U4 = MAX1558H_TDFN_10P: IC LIN SW USB ACTIVE HIGH DUAL 2.7-5.5V TDFN10; AGILE_PN: 312-80581; CAD_APPROVED: Yes; HEIGHT: 0.8MM; MFG_NAME01: MAXIM; MFG_PN01: MAX1558HETB+T; ROHS: Yes
U21 = T1023_BGA_525P: SUBASSEMBLY IC MPU T1023 POWERPC QORIQ 1V 1.2GHZ FCPBGA525 + SKT 525 BGA SMT 0.8MM 90H -- + HEATSINK; AGILE_PN: 750-77603; CAD_APPROVED: Yes; HEIGHT: 33.2MM; MFG_NAME01: Subassembly; MFG_PN01: 211-79483,330-76995,901-76858; ROHS: Yes; FPLIST: SKT_BGA525_0P8_58P6SQ_SM,skt_bga525_0p8mm_59x59_NSP
U40 = SRV05-4: DIODE TVS ARRAY 12A 5V 300W SOT23_S6; AGILE_PN: 480-75205; CAD_APPROVED: Yes; HEIGHT: 1.45mm; MFG_NAME01: SEMTECH CORP; MFG_PN01: SRV05-4.TCT; ROHS: Yes
C81 C293 C298 C310 = CAP_NP: CAP CER 0.01UF 16V 20% X7R 0402; AGILE_PN: 150-30082; CAD_APPROVED: Yes; FPLIST: CC0402_25,CC0402_HD,0402_CC; HEIGHT: 0.56MM; MFG_NAME01: AVX; MFG_PN01: 0402YC103MAT2A; ROHS: Yes; Tolerance: 20%; VOLTAGE: 16V
C82 C112 C114 C117 C297 C337-C341 C343 C346-C354 C359-C364 C371-C375 C378 C379 C382-C385 C387-C390 C392-C394 C396 C406 C407 C412-C416 C418-C420 C424 C426 C430-C433 C436-C438 C441 C445-C447 C454 C459 C483 C484 C488 C491 C527 C529 C543 = CAP_NP: CAP CER 0.1UF 6.3V 10% X5R 0201; AGILE_PN: 150-75429; CAD_APPROVED: Yes; FPLIST: CC0201,CC0201_HD,CC0201_3PIN,0201_CC; HEIGHT: 0.33MM; MFG_NAME01: MURATA; MFG_PN01: GRM033R60J104KE19D; ROHS: Yes; Tolerance: 10%; VOLTAGE: 6.3V
C311 C434 C435 C442 C453 = CAP_NP: CAP CER 0.01uF 6.3V 10% X5R 0201; AGILE_PN: 150-78890; CAD_APPROVED: Yes; FPLIST: CC0201,CC0201_HD,CC0201_3PIN,0201_CC; HEIGHT: 0.33MM; MFG_NAME01: Murata; MFG_PN01: GRM033R60J103KA01D; ROHS: Yes; Tolerance: 10%; VOLTAGE: 6.3V
C328 C334 C358 C404 C425 C450 C464 = CAP_NP: CAP CER 3000pF 50V 10% C0G 0603; AGILE_PN: 150-79452; CAD_APPROVED: Yes; FPLIST: CC0603_OV,CC0603,0603_CC; HEIGHT: 0.87MM; MFG_NAME01: KEMET; MFG_PN01: C0603C302K5GACTU; ROHS: Yes; Tolerance: 10%; VOLTAGE: 50V
C335 C336 C356 C357 C401 C402 C422 C423 C451 C452 = CAP_NP: CAP CER 2.2uF 10V 10% X5R 0402; AGILE_PN: 150-78974; CAD_APPROVED: Yes; FPLIST: CC0402_25,CC0402_HD,0402_CC; HEIGHT: 0.55 MM; MFG_NAME01: TDK; MFG_PN01: C1005X5R1A225K; ROHS: Yes; Tolerance: 10%; VOLTAGE: 10V
C333 C342 C345 C380 C397-C400 C449 = CAP_NP: CAP CER 1UF 6.3V 20% X5R 0402; AGILE_PN: 150-78002; CAD_APPROVED: Yes; FPLIST: CC0402_25,CC0402_HD,0402_CC; HEIGHT: 0.55MM; MFG_NAME01: MURATA; MFG_PN01: GRM155R60J105ME19D; ROHS: Yes; Tolerance: 20%; VOLTAGE: 6.3V
FL1 FL2 = NFM18PC225B1A3: CAP FILTER EMI 2.2uF 10V 20% -- 0603; AGILE_PN: 150-79428; CAD_APPROVED: Yes; HEIGHT: 0.9MM; MFG_NAME01: Murata; MFG_PN01: NFM18PC225B1A3B; ROHS: Yes; VOLTAGE: 10V
J10 J11 = CONN_HDR_2X1: HDR 1X2 TH 100MIL SP 338H SN 100L; AGILE_PN: 210-80102; CAD_APPROVED: Yes; HEIGHT: 8.58MM; MFG_NAME01: SAMTEC; MFG_PN01: TSW-102-07-T-S; ROHS: Yes
L27-L29 = BEAD_FERRITE: IND FER BEAD 120OHM@100MHZ 2A 25% 0603; AGILE_PN: 180-30008; CAD_APPROVED: Yes; FPLIST: IND_0603,0603_CC; HEIGHT: 0.95MM; MFG_NAME01: MURATA; MFG_PN01: BLM18PG121SH1; PART_TYPE: FERRITE; ROHS: Yes; Tolerance: 25%
C329 C465 = CAP_NP: CAP CER 4.7UF 10V 10% X5R 0603; AGILE_PN: 150-77975; CAD_APPROVED: Yes; FPLIST: CC0603_OV,CC0603,0603_CC; HEIGHT: 0.9MM; MFG_NAME01: TAIYO YUDEN; MFG_PN01: LMK107BJ475KA-T; ROHS: Yes; Tolerance: 10%; VOLTAGE: 10V
C330 C467 = MOT_CAP: CAP CER 47UF 16V 10% X5R 1210; AGILE_PN: 150-75908; CAD_APPROVED: Yes; FPLIST: CC1210,1210_CC; HEIGHT: 2.7 mm; MFG_NAME01: MURATA; MFG_PN01: GRM32ER61C476KE15L; ROHS: Yes; Tolerance: 10%; VOLTAGE: 16V
R273 R274 R331 = RES: RES MF 5.10 OHM 1/16W 1% 0402; AGILE_PN: 470-30609; CAD_APPROVED: Yes; FPLIST: RC0402_25,RC0402_HD,0402_CC; HEIGHT: 0.40 MM; MFG_NAME01: KOA SPEER; MFG_PN01: RK73H1ETTP5R10F; ROHS: Yes; Tolerance: 1%
R294 R330 = RES: RES MF 0.033 OHM 1/10W 1% 0603; AGILE_PN: 470-80944; CAD_APPROVED: Yes; FPLIST: RC0603_OV,RC0603,0603_CC; HEIGHT: 0.55MM; MFG_NAME01: YAGEO AMERICA; MFG_PN01: RL0603FR-070R033L; ROHS: Yes; Tolerance: 1%
BH1-BH4 = MOUNT_HOLE: MOUNTING HOLE CIRC DRILL 125 CIRC PAD 175 PLATED TRHU HOLE, no part to order; AGILE_PN: 280-75694; CAD_APPROVED: Yes; HEIGHT: 0 MM; MFG_NAME01: FOOTPRINT ONLY; MFG_PN01: FOOTPRINT ONLY; ROHS: Yes
BT1 = BATTERY_SKT_3V: BATTERY HOLDER CR2032 3V TH; AGILE_PN: 801-75534; CAD_APPROVED: Yes; HEIGHT: 22.9MM; MFG_NAME01: WIN WIN PRECISION INDUSTRIAL CO. LTD; ROHS: Yes
C60 = CAP_NP: CAP CER 0.1UF 25V 10% X5R 0402; AGILE_PN: 150-78633; CAD_APPROVED: Yes; FPLIST: CC0402_25,CC0402_HD,0402_CC; HEIGHT: 0.55MM; MFG_NAME01: YAGEO AMERICA; MFG_PN01: CC0402KRX5R8BB104; ROHS: Yes; SIGNAL_MODEL: DEFAULT_CAPACITOR_2.2e+06pF_2_1; TOL: 10%; Tolerance: 10%; VOLTAGE: 25V
C66 C286 C646 C647 = CAP_NP: CAP CER 0.1UF 25V 10% X5R 0402; AGILE_PN: 150-78633; CAD_APPROVED: Yes; FPLIST: CC0402_25,CC0402_HD,0402_CC; HEIGHT: 0.55MM; MFG_NAME01: YAGEO AMERICA; MFG_PN01: CC0402KRX5R8BB104; ROHS: Yes; SIGNAL_MODEL: CAP_NP_CC0402_25_0_55MM_150_762_0_01uF; TOL: 10%; Tolerance: 10%; VOLTAGE: 25V
L3 L5-L7 = INDUCTOR: IND FER 1000 OHM@100MHZ 250MA 25% 0402; AGILE_PN: 180-76315; CAD_APPROVED: Yes; FPLIST: IND_0402,IND0402_CC; Function: UART; HEIGHT: 0.55MM; MFG_NAME01: MURATA; MFG_PN01: BLM15HG102SN1D; PART_TYPE: FERRITE; ROHS: Yes; SIGNAL_MODEL: DEFAULT_RESISTOR_1000OHM_2_1; TOL: 25%; Tolerance: 25%
P1 = RJ45-8: CON 8 RJ-45 SHLD RA TH 40MIL SP 594H AU 143L; AGILE_PN: 210-79665; CAD_APPROVED: Yes; HEIGHT: 15.08MM; MFG_NAME01: ANYTRONIC CORPORATION LIMITED; MFG_PN01: 3520B811014#46-3LF; ROHS: Yes
R6 R7 = RES: RES MF 4.7K 1/16W 5% 0402; AGILE_PN: 470-75626; ASSY_OPT: DNP; CAD_APPROVED: Yes; FPLIST: RC0402_25,RC0402_HD,0402_CC; Function: UART; HEIGHT: 0.41mm; MFG_NAME01: KOA SPEER; MFG_PN01: RK73B1ETTP472J; ROHS: Yes; SIGNAL_MODEL: DEFAULT_RESISTOR_4700OHM_2_1; TOL: 5%; Tolerance: 5%
U2 = SP3232E: IC XCVR RS232 120KBPS 3.0-5.5V SSOP16; AGILE_PN: 312-77064; CAD_APPROVED: Yes; HEIGHT: 1.99MM; MFG_NAME01: SIPEX; MFG_PN01: SP3232ECA-L; ROHS: Yes
U10 = DS1339: IC CLK RTC I2C 3.3V USOP8; AGILE_PN: 315-76726; CAD_APPROVED: Yes; HEIGHT: 1.1MM; MFG_NAME01: DALLAS SEMICONDUCTOR; ROHS: Yes
U13 = M24256: IC MEM EEPROM 256KBIT 2.5-5.5V TSSOP8; AGILE_PN: 334-77218; CAD_APPROVED: Yes; HEIGHT: 1.2MM; MFG_NAME01: ST MICROELECTRONICS; ROHS: Yes
U48 = TCA6408A_16P: IC I/O EXPANDER 8-BIT I2C SMBUS 1.65-5.5V TSSOP16; AGILE_PN: 312-80924; CAD_APPROVED: Yes; HEIGHT: 1,20MM; MFG_NAME01: TEXAS INSTRUMENTS; ROHS: Yes
Y4 = XTAL: XTAL 32.768KHZ PAR 20PPM -- SMT; AGILE_PN: 230-77966; CAD_APPROVED: Yes; HEIGHT: 2.45 MM; MFG_NAME01: PERICOM SEMICONDUCTOR; MFG_PN01: G33270005; ROHS: Yes

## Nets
AVDD_CGA1: C297.1 C298.1 C299.1 C310.1 C311.1 C312.1 C348.1 C350.1 C352.1 C353.1 C354.1 C385.1 C392.1 C407.1 C424.1 C431.1 C647.1 J10.2 J11.1 L29.2 R142.1 R143.2 R144.2 R150.1 R153.1 R154.1 R163.1 R272.1 R273.1 R274.1 R277.2 R279.1 R281.1 R283.1 R289.1 R290.2 R323.1 R328.1 R331.1 R356.1 R367.1 R368.1 R420.2 R421.2 R422.2 R423.1 R424.1 U21.H11(OVDD1) U21.H12(OVDD2) U21.H13(OVDD3) U21.H14(OVDD4) U21.H15(OVDD5) U21.J8(TH_VDD) U21.L8(CVDD) U21.P8(LVDD1) U21.R8(LVDD2) U21.T8(LVDD3) U44.13(VCCB) U48.16(VCCP) ; also on sheet 6 7 20 21 24
AVDD_SD1_PLL1: FL2.3(OUT_IN) R294.2 R329.2 R330.2 ; also on sheet 24
GND: BH1.1 BH2.1 BH3.1 BH4.1 BT1.3(neg) C3.2 C5.2 C11.2 C12.2 C14.2 C60.2 C66.2 C81.2 C82.2 C112.2 C114.2 C115.2 C117.2 C182.1 C193.1 C286.2 C292.2 C293.2 C297.2 C298.2 C299.2 C310.2 C311.2 C312.2 C315.2 C316.2 C320.2 C331.2 C333.2 C334.2 C335.1 C336.1 C337.2 C338.2 C339.2 C340.2 C341.2 C342.2 C343.2 C345.2 C346.2 C347.2 C348.2 C349.2 C350.2 C351.2 C352.2 C353.2 C354.2 C356.1 C357.1 C358.2 C359.2 C360.2 C361.2 C362.2 C363.2 C364.2 C367.2 C368.2 C369.2 C371.2 C372.2 C373.2 C374.2 C375.2 C376.2 C378.2 C379.2 C380.2 C382.2 C383.2 C384.2 C385.2 C387.2 C388.2 C389.2 C390.2 C392.2 C393.2 C394.2 C395.2 C396.2 C397.2 C398.2 C399.2 C400.2 C401.1 C402.1 C404.2 C406.2 C407.2 C410.2 C412.2 C413.2 C414.2 C415.2 C416.2 C418.2 C419.2 C420.2 C422.1 C423.1 C424.2 C425.2 C426.2 C430.2 C431.2 C432.2 C433.2 C434.2 C435.2 C436.2 C437.2 C438.2 C441.2 C442.2 C445.2 C446.2 C447.2 C449.2 C450.2 C451.1 C452.1 C453.2 C454.2 C459.2 C462.2 C468.2 C470.2 C471.2 C483.2 C484.2 C488.2 C491.2 C527.2 C529.2 C543.2 C646.2 C647.2 FL1.2(GND) FL2.2(GND) J13.12 J13.16 L2.1 P1.4 P1.5 Q16.2(EMITTER) Q28.2(EMITTER) R6.2 R7.2 R10.2 R19.2 R25.2 R98.2 R101.2 R269.1 R270.1 R271.2 R278.1 R284.2 R298.1 R305.2 R336.2 R337.2 R346.2 R349.2 R353.1 R425.2 R426.2 U2.15(GND) U4.8(GND) U4.11(EPAD) U10.4(GND) U13.1(E0) U13.2(E1) U13.3(E2) U13.4(VSS) U13.7(~{WC}) U21.A2(GND001) U21.A18(GND002) U21.A22(GND003) U21.AA6(SD_GND20) U21.AA7(SD_GND21) U21.AA8(SD_GND22) U21.AA9(SD_GND23) U21.AA10(SD_GND24) U21.AA11(SD_GND25) U21.AA12(SD_GND26) U21.AA13(SD_GND27) U21.AA14(SD_GND28) U21.AA15(SD_GND29) U21.AA16(SD_GND30) U21.AA17(SD_GND31) U21.AB1(GND108) U21.AB4(GND109) U21.AB6(SD_GND32) U21.AB8(SD_GND33) U21.AB10(SD_GND34) U21.AB12(SD_GND35) U21.AB15(SD_GND36) U21.AB17(SD_GND37) U21.AC2(GND110) U21.AC6(SD_GND38) U21.AC8(SD_GND39) U21.AC10(SD_GND40) U21.AC12(SD_GND41) U21.AC15(SD_GND42) U21.AC17(SD_GND43) U21.B1(GND004) U21.B3(GND005) U21.B7(GND006) U21.B10(GND007) U21.B13(GND008) U21.B16(GND009) U21.B18(GND010) U21.B20(GND011) U21.C1(USB_AGND01) U21.C2(USB_AGND02) U21.C4(GND012) U21.C19(GND013) U21.C22(GND014) U21.D3(USB_AGND03) U21.D18(GND015) U21.D20(GND016) U21.E1(USB_AGND04) U21.E2(USB_AGND05) U21.E6(GND017) U21.E9(GND018) U21.E12(GND019) U21.E15(GND020) U21.E19(GND021) U21.E22(GND022) U21.F3(USB_AGND06) U21.F17(GND023) U21.F20(GND024) U21.G1(USB_AGND07) U21.G2(USB_AGND08) U21.G6(GND025) U21.G9(USB_AGND09) U21.G10(GND026) U21.G11(GND027) U21.G12(GND028) U21.G13(GND029) U21.G14(GND030) U21.G15(GND031) U21.G17(TD1_ANODE) U21.G18(TD1_CATHODE) U21.G19(GND032) U21.G22(GND033) U21.H2(GND034) U21.H7(USB_AGND10) U21.H16(GND035) U21.H17(GND036) U21.H20(GND037) U21.J5(GND038) U21.J7(GND039) U21.J9(GND040) U21.J11(GND041) U21.J13(GND042) U21.J16(GND043) U21.J19(GND044) U21.J22(GND045) U21.K7(GND046) U21.K10(GND047) U21.K12(GND048) U21.K14(GND049) U21.K16(GND050) U21.K17(GND051) U21.K18(GND052) U21.K20(GND053) U21.L2(GND054) U21.L5(GND055) U21.L7(GND056) U21.L9(GND057) U21.L11(GND058) U21.L13(GND059) U21.L16(GND060) U21.L18(GND061) U21.L22(GND062) U21.M7(GND063) U21.M10(GND064) U21.M12(GND065) U21.M14(GND066) U21.M16(GND067) U21.M18(GND068) U21.M21(GND069) U21.N7(GND070) U21.N9(GND071) U21.N11(GND072) U21.N13(GND073) U21.N16(GND074) U21.N17(GND075) U21.N18(GND076) U21.P2(GND077) U21.P7(GND078) U21.P10(GND079) U21.P12(GND080) U21.P14(GND081) U21.P16(GND082) U21.P18(GND083) U21.P20(GND084) U21.P22(GND085) U21.R5(GND086) U21.R7(GND087) U21.R9(GND088) U21.R11(GND089) U21.R13(GND090) U21.R16(GND091) U21.R17(GND092) U21.T7(GND093) U21.T10(GND094) U21.T14(GND095) U21.T16(GND096) U21.T22(GND097) U21.U2(GND098) U21.U5(GND099) U21.U8(GND100) U21.U9(GND101) U21.U11(SD_GND01) U21.U12(SD_GND02) U21.U13(SD_GND03) U21.U15(SD_GND04) U21.U16(GND102) U21.U23(GND103) U21.V4(GND104) U21.V6(SD_GND05) U21.V7(SD_GND06) U21.V9(SD_GND07) U21.V16(SD_GND08) U21.W6(SD_GND09) U21.W8(SD_GND10) U21.W10(SD_GND11) U21.W12(SD_GND12) U21.W15(SD_GND13) U21.W17(GND105) U21.Y2(GND106) U21.Y5(GND107) U21.Y6(SD_GND14) U21.Y8(SD_GND15) U21.Y10(SD_GND16) U21.Y12(SD_GND17) U21.Y15(SD_GND18) U21.Y17(SD_GND19) U40.2(A2) U44.6(GND1) U44.7(GND2) U44.8(~{OE}) U48.2(ADDR) U48.8(GND) ; also on sheet 5 6 7 14 15 16 17 18 19 20 21 22 23 24
GND_EARTH: J2.S1(SGND1) J2.S2(SGND2) P1.9 P1.10 ; also on sheet 14 15 17
VBAT_OPT1: R84.1 U10.3(VBACKUP)
AQR105_VA12: C339.1 R227.2 R229.2 U21.P5(TVDD) ; also on sheet 16 17 21 23
AQR_INT_n: U21.T3(IRQ3/GPIO1_23) ; also on sheet 16
COP_CKSTP_OUT_n: J13.15 Q9.3(COLLECTOR) R366.1
COP_HRST: J13.13 Q24.2(EMITTER) R365.1
COP_SRST: J13.11 Q8.2(EMITTER) R364.1
COP_TCK: J13.7 R362.1 U44.3(A3)
COP_TDI: J13.3 R360.1 U44.1(A1)
COP_TDO: J13.1 U44.2(A2)
COP_TMS: J13.9 R363.1 U44.4(A4)
COP_TRST: J13.4 Q10.2(EMITTER) R369.1
CPU_RST_REQ: U21.F6(~{RESET_REQ}) ; also on sheet 21
DCDC2_3V3: C66.1 C182.2 C286.1 C292.1 C293.1 C346.1 C351.1 C646.1 L27.2 R23.2 R86.1 R198.2 R259.1 R260.1 R264.1 R265.1 R360.2 R362.2 R363.2 R364.2 R365.2 R366.2 R369.2 R370.1 R400.1 R466.2 U2.16(VCC) U10.8(VCC) U13.8(VCC) U21.M8(DVDD1) U21.N8(DVDD2) U44.16(VCCA) U48.1(VCCI) ; also on sheet 6 7 14 15 18 19 20 21 23 24
DCDC_1V0: C341.1 C345.1 C360.1 C362.1 C363.1 C364.1 C367.1 C368.1 C369.1 C372.1 C373.1 C374.1 C376.1 C378.1 C379.1 C380.1 C383.1 C387.1 C388.1 C393.1 C394.1 C395.1 C396.1 C397.1 C398.1 C399.1 C400.1 C410.1 C412.1 C413.1 C414.1 C415.1 C416.1 C418.1 C420.1 C441.1 L28.2 U21.J10(VDD01) U21.J12(VDD02) U21.J14(VDD03) U21.K9(VDD04) U21.K11(VDD05) U21.K13(VDD06) U21.L10(VDD07) U21.L12(VDD08) U21.L14(VDD09) U21.M9(VDD10) U21.M11(VDD11) U21.M13(VDD12) U21.N10(VDD13) U21.N12(VDD14) U21.N14(VDD15) U21.P9(VDD16) U21.P11(VDD17) U21.P13(VDD18) U21.R10(VDD19) U21.R12(VDD20) U21.R14(VDD21) U21.T9(VDD22) ; also on sheet 20
DCDC_5V0: U4.1(INA) ; also on sheet 23
DDR4_VDD: C112.1 C114.1 C115.1 C117.1 C430.1 C432.1 C433.1 C434.1 C435.1 C436.1 C437.1 C438.1 C442.1 C445.1 C446.1 C447.1 C453.1 C454.1 C459.1 C468.1 C470.1 C471.1 C483.1 C484.1 C488.1 C491.1 C527.1 C529.1 C543.1 U21.AB18(G1VDD19) U21.AB20(G1VDD20) U21.AB22(G1VDD21) U21.J15(G1VDD01) U21.K15(G1VDD02) U21.L15(G1VDD03) U21.M15(G1VDD04) U21.N15(G1VDD05) U21.P15(G1VDD06) U21.P19(G1VDD07) U21.R15(G1VDD08) U21.R21(G1VDD09) U21.T15(G1VDD10) U21.T17(G1VDD11) U21.T19(G1VDD12) U21.V18(G1VDD13) U21.V20(G1VDD14) U21.V22(G1VDD15) U21.Y18(G1VDD16) U21.Y20(G1VDD17) U21.Y22(G1VDD18) ; also on sheet 5 24
EC1_CLK_125M: U21.W4(EC1_GTX_CLK125/GPIO3_17) ; also on sheet 14
EC1_PHY_INT_n: R281.2 U21.Y3(IRQ2) ; also on sheet 14
EC1_RXC: U21.T1(EC1_RX_CLK/GPIO3_23) ; also on sheet 14
EC1_RXCTL: U21.W1(EC1_RX_DV/GPIO3_22) ; also on sheet 14
EC1_RXD0: U21.V2(EC1_RXD0/GPIO3_21) ; also on sheet 14
EC1_RXD1: U21.V1(EC1_RXD1/GPIO3_20) ; also on sheet 14
EC1_RXD2: U21.U1(EC1_RXD2/GPIO3_19) ; also on sheet 14
EC1_RXD3: U21.T2(EC1_RXD3/GPIO3_18) ; also on sheet 14
EC1_TXC: R285.1 ; also on sheet 14
EC1_TXCTL: R288.1 ; also on sheet 14
EC1_TXD0: R296.1 ; also on sheet 14
EC1_TXD1: R287.1 ; also on sheet 14
EC1_TXD2: R295.1 ; also on sheet 14
EC1_TXD3: R286.1 ; also on sheet 14
EMI1_MDC: R277.1 U21.W2(EMI1_MDC/GPIO3_08) ; also on sheet 14 15
EMI1_MDIO: R279.2 U21.Y1(EMI1_MDIO/GPIO3_09) ; also on sheet 14 15
EMI2_MDC: R227.1 U21.P3(EMI2_MDC) ; also on sheet 16
EMI2_MDIO: R229.1 U21.P4(EMI2_MDIO) ; also on sheet 16
EVDD: C81.1 C82.1 C320.1 C349.1 U21.K8(EVDD) ; also on sheet 7 20
GPIO1_14_eMMC_SEL_n: R290.1 U21.C17(RTC/GPIO1_14) ; also on sheet 6 7
GPIO3_0_WAKE_L: R289.2 R431.1 R432.1 ; also on sheet 18
GPIO3_1_CLKREQ_L: R421.1 U21.AA3(TSEC_1588_TRIG_IN1/GPIO3_01/EC2_TXD2) ; also on sheet 18
GPIO3_2_WAKE_L: R420.1 U21.AA1(EC2_GTX_CLK125/GPIO3_02/TSEC_1588_TRIG_IN2) ; also on sheet 18
GPIO3_3_CLKREQ_L: R422.1 U21.AB2(TSEC_1588_ALARM_OUT1/GPIO3_03/EC2_RX_CLK) ; also on sheet 18
I2C1_SCL: R265.2 U10.6(SCL) U13.6(SCL) U21.N1(IIC1_SCL) ; also on sheet 18 24
I2C1_SDA: R260.2 U10.5(SDA) U13.5(SDA) U21.N2(IIC1_SDA) ; also on sheet 18 24
I2C2_SCL: R264.2 U21.M1(GPIO4_27/IIC2_SCL) U48.14(SCL) ; also on sheet 18 20 21
I2C2_SDA: R259.2 U21.M2(GPIO4_28/IIC2_SDA) U48.15(SDA) ; also on sheet 18 20 21
IFC_A23_INVERT: U48.6(P2) ; also on sheet 6
IFC_A24_INVERT: U48.5(P1) ; also on sheet 6
IFC_A25_INVERT: U48.4(P0) ; also on sheet 6
JTAG_TCK: U21.E18(TCK) U44.10(B3)
JTAG_TDI: U21.C18(TDI) U44.12(B1)
JTAG_TDO: U21.D17(TDO) U44.11(B2)
JTAG_TMS: U21.E17(TMS) U44.9(B4)
LANEA_RX_N: C365.2 ; also on sheet 18
LANEA_RX_P: C377.2 ; also on sheet 18
LANEA_TX_N: C344.1 ; also on sheet 18
LANEA_TX_P: C355.1 ; also on sheet 18
LANEB_RX_N: C366.2 ; also on sheet 16
LANEB_RX_P: C381.2 ; also on sheet 16
LANEB_TX_N: U21.Y11(SD1_TX1_N) ; also on sheet 16
LANEB_TX_P: U21.W11(SD1_TX1_P) ; also on sheet 16
LANEC_RX_N: C427.2 ; also on sheet 18
LANEC_RX_P: C409.2 ; also on sheet 18
LANEC_TX_N: C403.1 ; also on sheet 18
LANEC_TX_P: C391.1 ; also on sheet 18
LANED_RX_N: U21.AB14(SD1_RX3_N) ; also on sheet 15
LANED_RX_P: U21.AC14(SD1_RX3_P) ; also on sheet 15
LANED_TX_N: C417.1 ; also on sheet 15
LANED_TX_P: C429.1 ; also on sheet 15
LDO_1V0: FL1.3(OUT_IN) R309.2 ; also on sheet 20
nUART_CTS: L3.2 P1.8
nUART_RTS: L5.2 P1.1
PORESET: Q24.3(COLLECTOR) Q25.3(COLLECTOR) R356.2 U21.B5(~{PORESET})
RESET: Q11.2(EMITTER) Q25.2(EMITTER) ; also on sheet 7 14 15 18 21
RS232_CTS0: L3.1 U2.8(R2IN)
RS232_RTS0: L5.1 U2.7(T2OUT)
RS232_RXD0: L6.1 U2.13(R1IN)
RS232_TXD0: L7.1 U2.14(T1OUT)
RTC_INT_n: R86.2 U10.7(SQW~{/INT}) U21.R4(IRQ5/GPIO1_25)
RTC_XI: U10.1(X1) Y4.1
RTC_XO: U10.2(X2) Y4.2
SD_CLK1_N: U21.AB7(SD1_REF_CLK1_N) ; also on sheet 19
SD_CLK1_P: U21.AC7(SD1_REF_CLK1_P) ; also on sheet 19
SD_CLK2_N: U21.AB16(SD1_REF_CLK2_N) ; also on sheet 19
SD_CLK2_P: U21.AC16(SD1_REF_CLK2_P) ; also on sheet 19
SDHC_VS: R270.2 U21.C5(IRQ1/SDHC_VS/USBCLK) ; also on sheet 20
SGMII_PHY_INT_n: R272.2 U21.D5(IRQ0) ; also on sheet 15
SYS_REFCLK_N: U21.B4(~{DIFF_SYSCLK}) ; also on sheet 19
SYS_REFCLK_P: U21.A4(DIFF_SYSCLK) ; also on sheet 19
TEST_SEL_N: R283.2 U21.F8(~{TEST_SEL}) ; also on sheet 6
UART1_CTS: R6.1 U2.9(R2OUT) U21.R3(GPIO1_21/~{UART1_CTS}/UART3_SIN)
UART1_RTS: R7.1 U2.10(T2IN) U21.R2(GPIO1_19/~{UART1_RTS}/UART3_SOUT)
UART1_RXD: U2.12(R1OUT) U21.P1(GPIO1_17/UART1_SIN)
UART1_TXD: U2.11(T1IN) U21.R1(GPIO1_15/UART1_SOUT)
UART_SIN: L6.2 P1.6
UART_SOUT: L7.2 P1.3
N17321635: Q9.2(EMITTER) R143.1 U21.E16(~{CKSTP_OUT})
N17423556: J13.6 R370.2
N23886013: C5.1 U2.2(V+)
N23886021: C8.2 U2.3(C1-)
N23886023: C8.1 U2.1(C1+)
N23886031: C3.1 U2.6(V-)
N23886069: C4.2 U2.4(C2+)
N23886074: C4.1 U2.5(C2-)
N23887688: BT1.1(pos1) BT1.2(pos2) C60.1 R84.2
N24220381: C347.1 C356.2 C357.2 C358.1 C359.1 L28.1 U21.G8(USB_SVDD1) U21.H8(USB_SVDD2)
N24221237: C334.1 C335.2 C336.2 C337.1 C343.1 L27.1 U21.D4(USB_HVDD1) U21.G7(USB_HVDD2)
N24221789: C361.1 C371.1 C401.2 C402.2 C404.1 L29.1 U21.H9(USB_OVDD1) U21.H10(USB_OVDD2)
N24222945: TP44.1(Pin1) U21.G16(SENSEVDD)
N24222963: TP36.1(Pin1) U21.F16(SENSEGND)
N24242061: C338.1 J10.1 R98.1 U21.H5(PROG_SFP)
N24242100: C340.1 J11.2 R101.1 U21.K5(PROG_MTR)
N24244080: R346.1 U21.H18(FA_VL)
N24245830: C384.1 C390.1 C419.1 C422.2 C423.2 C425.1 FL1.1(IN_OUT) U21.T11(S1VDD1) U21.T12(S1VDD2) U21.T13(S1VDD3)
N24247836: C375.1 C382.1 C389.1 C406.1 C426.1 C450.1 C451.2 C452.2 FL2.1(IN_OUT) U21.V10(X1VDD1) U21.V11(X1VDD2) U21.V12(X1VDD3) U21.V13(X1VDD4) U21.V14(X1VDD5)
N24271003: C315.1 C333.1 R273.2 U21.H6(AVDD_CGA1)
N24271010: C316.1 C342.1 R274.2 U21.J6(AVDD_PLAT)
N24271066: C449.1 C462.1 R331.2 U21.L17(AVDD_D1)
N24275030: C328.1 C329.1 C330.1 R294.1 U21.Y7(AVDD_SD1_PLL1)
N24275210: C464.1 C465.1 C467.1 R330.1 U21.Y16(AVDD_SD1_PLL2)
N24275332: C328.2 C329.2 C330.2 R305.1
N24275468: C464.2 C465.2 C467.2 R336.1
N24320723: R278.2 R288.2 U21.W3(EC1_TX_EN/GPIO3_15)
N24320726: C331.1 R285.2 U21.T4(EC1_GTX_CLK/GPIO3_16)
N24320797: R296.2 U21.V5(EC1_TXD0/GPIO3_14)
N24320800: R287.2 U21.V3(EC1_TXD1/GPIO3_13)
N24320803: R295.2 U21.U4(EC1_TXD2/GPIO3_12)
N24320806: R286.2 U21.U3(EC1_TXD3/GPIO3_11)
N24378188: L4.4 U21.D1(USB1_UDP)
N24378195: L4.1 U21.D2(USB1_UDM)
N24378208: J2.A3(DATA-) L4.3 U40.1(A1)
N24378216: J2.A2(DATA+) L4.2 U40.3(A3)
N24378377: J2.A1(VCC) L1.2 U40.5(A5)
N24378560: J2.A4(GND) L2.2
N24378635: C323.1 R298.2 U21.E3(USB_IBIAS_REXT)
N24378650: C323.2 R284.1
N24378685: R271.1 U21.C3(USB1_UID)
N24379174: R199.1 U21.E4(USB1_PWRFAULT)
N24379185: R25.1 U4.2(ONA) U21.F4(USB1_DRVVBUS)
N24379468: C11.1 C12.1 C14.1 D5.C(CATHODE) L1.1 R11.1 U4.10(OUTA)
N24379558: D5.A(ANODE) R10.1 R11.2 U21.B2(USB1_VBUSCLMP)
N24379631: R22.2 U4.9(~{FLTA})
N24380059: R19.1 U4.3(ISET)
N24380394: C193.2 Q16.3(COLLECTOR) R198.1 R199.2
N24389900: R297.1 U21.A5(GPIO1_13/ASLEEP)
N24390647: R323.2 U21.F9(~{SCAN_MODE})
N24391453: R328.2 U21.F19(~{TMP_DETECT})
N24392141: Q10.3(COLLECTOR) R163.2 R164.2 U21.F18(~{TRST})
N24402189: Q8.3(COLLECTOR) R150.2 U21.E8(~{HRESET})
N24418365: Q24.1(BASE) R367.2
N24422044: TP41.1(Pin1) U21.E7(CLK_OUT)
N24422127: R337.1 U21.H19(FA_ANALOG_G_V)
N24422137: R349.1 U21.J18(FA_ANALOG_PIN)
N24442993: R309.1 U21.W7(SD1_IMP_CAL_RX)
N24443017: R329.1 U21.V15(SD1_IMP_CAL_TX)
N24582130: C377.1 U21.AC9(SD1_RX0_P)
N24582194: C366.1 U21.AB11(SD1_RX1_N)
N24582197: C381.1 U21.AC11(SD1_RX1_P)
N24582200: C365.1 U21.AB9(SD1_RX0_N)
N24582275: C355.2 U21.W9(SD1_TX0_P)
N24582286: C344.2 U21.Y9(SD1_TX0_N)
N24582369: C403.2 U21.Y13(SD1_TX2_N)
N24582387: C391.2 U21.W13(SD1_TX2_P)
N24582412: TP30.1(Pin1) U21.V8(SD1_PLL1_TPA)
N24582419: TP28.1(Pin1) U21.U10(SD1_PLL1_TPD)
N24582434: TP37.1(Pin1) U21.W16(SD1_PLL2_TPA)
N24582441: TP42.1(Pin1) U21.U14(SD1_PLL2_TPD)
N24647838: Q25.1(BASE) R368.2
N24648256: Q10.1(BASE) R153.2
N24648262: Q11.1(BASE) R154.2
N24891529: R269.2 U21.A3(SYSCLK)
N24891545: R353.2 U21.J17(DDRCLK)
N24892246: Q8.1(BASE) R142.2
N25032157: Q28.1(BASE) R297.2
N25032334: Q9.1(BASE) R144.1
N25115909: C409.1 U21.AC13(SD1_RX2_P)
N25115912: C427.1 U21.AB13(SD1_RX2_N)
N25116015: C429.2 U21.W14(SD1_TX3_P)
N25116018: C417.2 U21.Y14(SD1_TX3_N)
N25168167: D18.C(CATHODE) Q28.3(COLLECTOR)
N25168313: D18.A(ANODE) R400.2
N25169246: Q16.1(BASE) R22.1 R23.1
N25440106: Q11.3(COLLECTOR) R164.1
N25614680: TP35.1(Pin1) U21.F7(~{EVT4})
N25614695: TP39.1(Pin1) U21.E5(~{EVT3})
N25614710: TP33.1(Pin1) U21.E10(~{EVT2})
N25614762: TP40.1(Pin1) U21.D6(~{EVT1})
N25614777: TP38.1(Pin1) U21.C6(~{EVT0})
N25614880: TP59.1(Pin1) U21.M5(GPIO1_16/UART2_SOUT)
N25617432: TP34.1(Pin1) U21.F10(~{IRQ_OUT}/~{EVT9})
N25617574: TP24.1(Pin1) U21.AA5(TSEC_1588_PULSE_OUT2/GPIO3_07/EC2_TX_EN)
N25617577: TP5.1(Pin1) U21.AA2(GPIO3_26/EC2_TXD3)
N25617583: R424.2 R425.1 U21.AA4(TSEC_1588_ALARM_OUT2/GPIO3_04/EC2_TXD0)
N25617586: R423.2 R426.1 U21.Y4(TSEC_1588_CLK_OUT/GPIO3_05/EC2_TXD1)
N25617589: TP8.1(Pin1) U21.AC3(TSEC_1588_PULSE_OUT1/GPIO3_06/EC2_RXD2)
N25617590: TP11.1(Pin1) U21.AC5(GPIO3_24/EC2_RX_DV)
N25617591: TP9.1(Pin1) U21.AC4(GPIO3_28/EC2_RXD1)
N25617592: TP7.1(Pin1) U21.AB3(GPIO3_27/EC2_RXD3)
N25617593: TP10.1(Pin1) U21.AB5(GPIO3_25/EC2_RXD0)
N26207329: TP60.1(Pin1) U21.N3(GPIO1_22/UART4_SIN/~{EVT8}/~{UART2_CTS})
N26207331: TP61.1(Pin1) U21.N4(GPIO1_20/UART4_SOUT/~{EVT7}/~{UART2_RTS})
N26318609: TP51.1(Pin1) U21.N5(GPIO1_18/UART2_SIN)
N26623758: R432.2 U21.W5(EC2_GTX_CLK/GPIO3_00/TSEC_1588_CLK_IN)
N26628373: R431.2 U21.L4(IRQ4/SDHC_CLK_SYNC_IN/GPIO1_24)
N26884619: R466.1 U48.3(~{RESET})

Not connected (* = marked no-connect by the designer): J13 2* 5* 8* 10* 14*; P1 2* 7*; U4 4(ONB)* 5(INB)* 6(OUTB)* 7(~{FLTB})*; U21 AB23(NC_DET)* F1(USB2_UDP)* F2(USB2_UDM)* F5(USB2_VBUSCLMP)* G3(USB2_UID)* G4(USB2_PWRFAULT)* G5(USB2_DRVVBUS)* K6(TH_TPA)* L6(NC)* M6(NC)* N6(NC)* P6(NC)* R6(NC)* T5(NC)* T6(NC)* U6(NC)* U7(NC)*; U40 4(A4)* 6(A6)*; U44 5(NC5)* 14(NC14)* 15(NC15)*; U48 7(P3)* 9(P4)* 10(P5)* 11(P6)* 12(P7)* 13(~{INT})*

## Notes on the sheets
sheet 8
- Need DNP R164
  For BSDL Test
- GPIO & INTTRUPT
- GPIO
- H
- L
- GPIO1_14
- SD/MMC Card
- eMMC
- GPIO1_16
- GPIO1_20
- GPIO1_22
- GPIO3_0
- PCIE1 wake
- GPIO3_1
- reserved
- GPIO3_2
- PCIE2 wake
- GPIO3_3
- reserved
- Rev B
- Rev D
- Rev E
- Rev F
- GPIO3_4
- Board version bit 1
- GPIO3_5
- Board version bit 0
- IRQ0
- 1G SGMII PHY
- GPIO3_04
- 0
- 0
- 1
- 1
- IRQ2
- RGMII PHY
- IRQ3
- 2.5G SGMII PHY
- GPIO3_05
- 0
- 1
- 0
- 1
- PCIE1 wake
- IRQ4
- IRQ5
- RTC
sheet 9
- SerDes LANE Assignment
  LANE A MINI-PCIe
  LANE B 2.5G SGMII
  LANE C MINI-PCIe
  LANE D 1G SGMII
sheet 10
- 90ohm match
- HOST MODE
sheet 13
- I2C EEPROM
- I2C1 ADDR: 1010000
  0X50
- I2C1 ADDR:1101000
  0X68
- ADDRESS:0X20
